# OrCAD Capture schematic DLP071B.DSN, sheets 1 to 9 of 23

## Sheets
1 PAGE21 - OUTPUT FMC CONNECTOR: size C
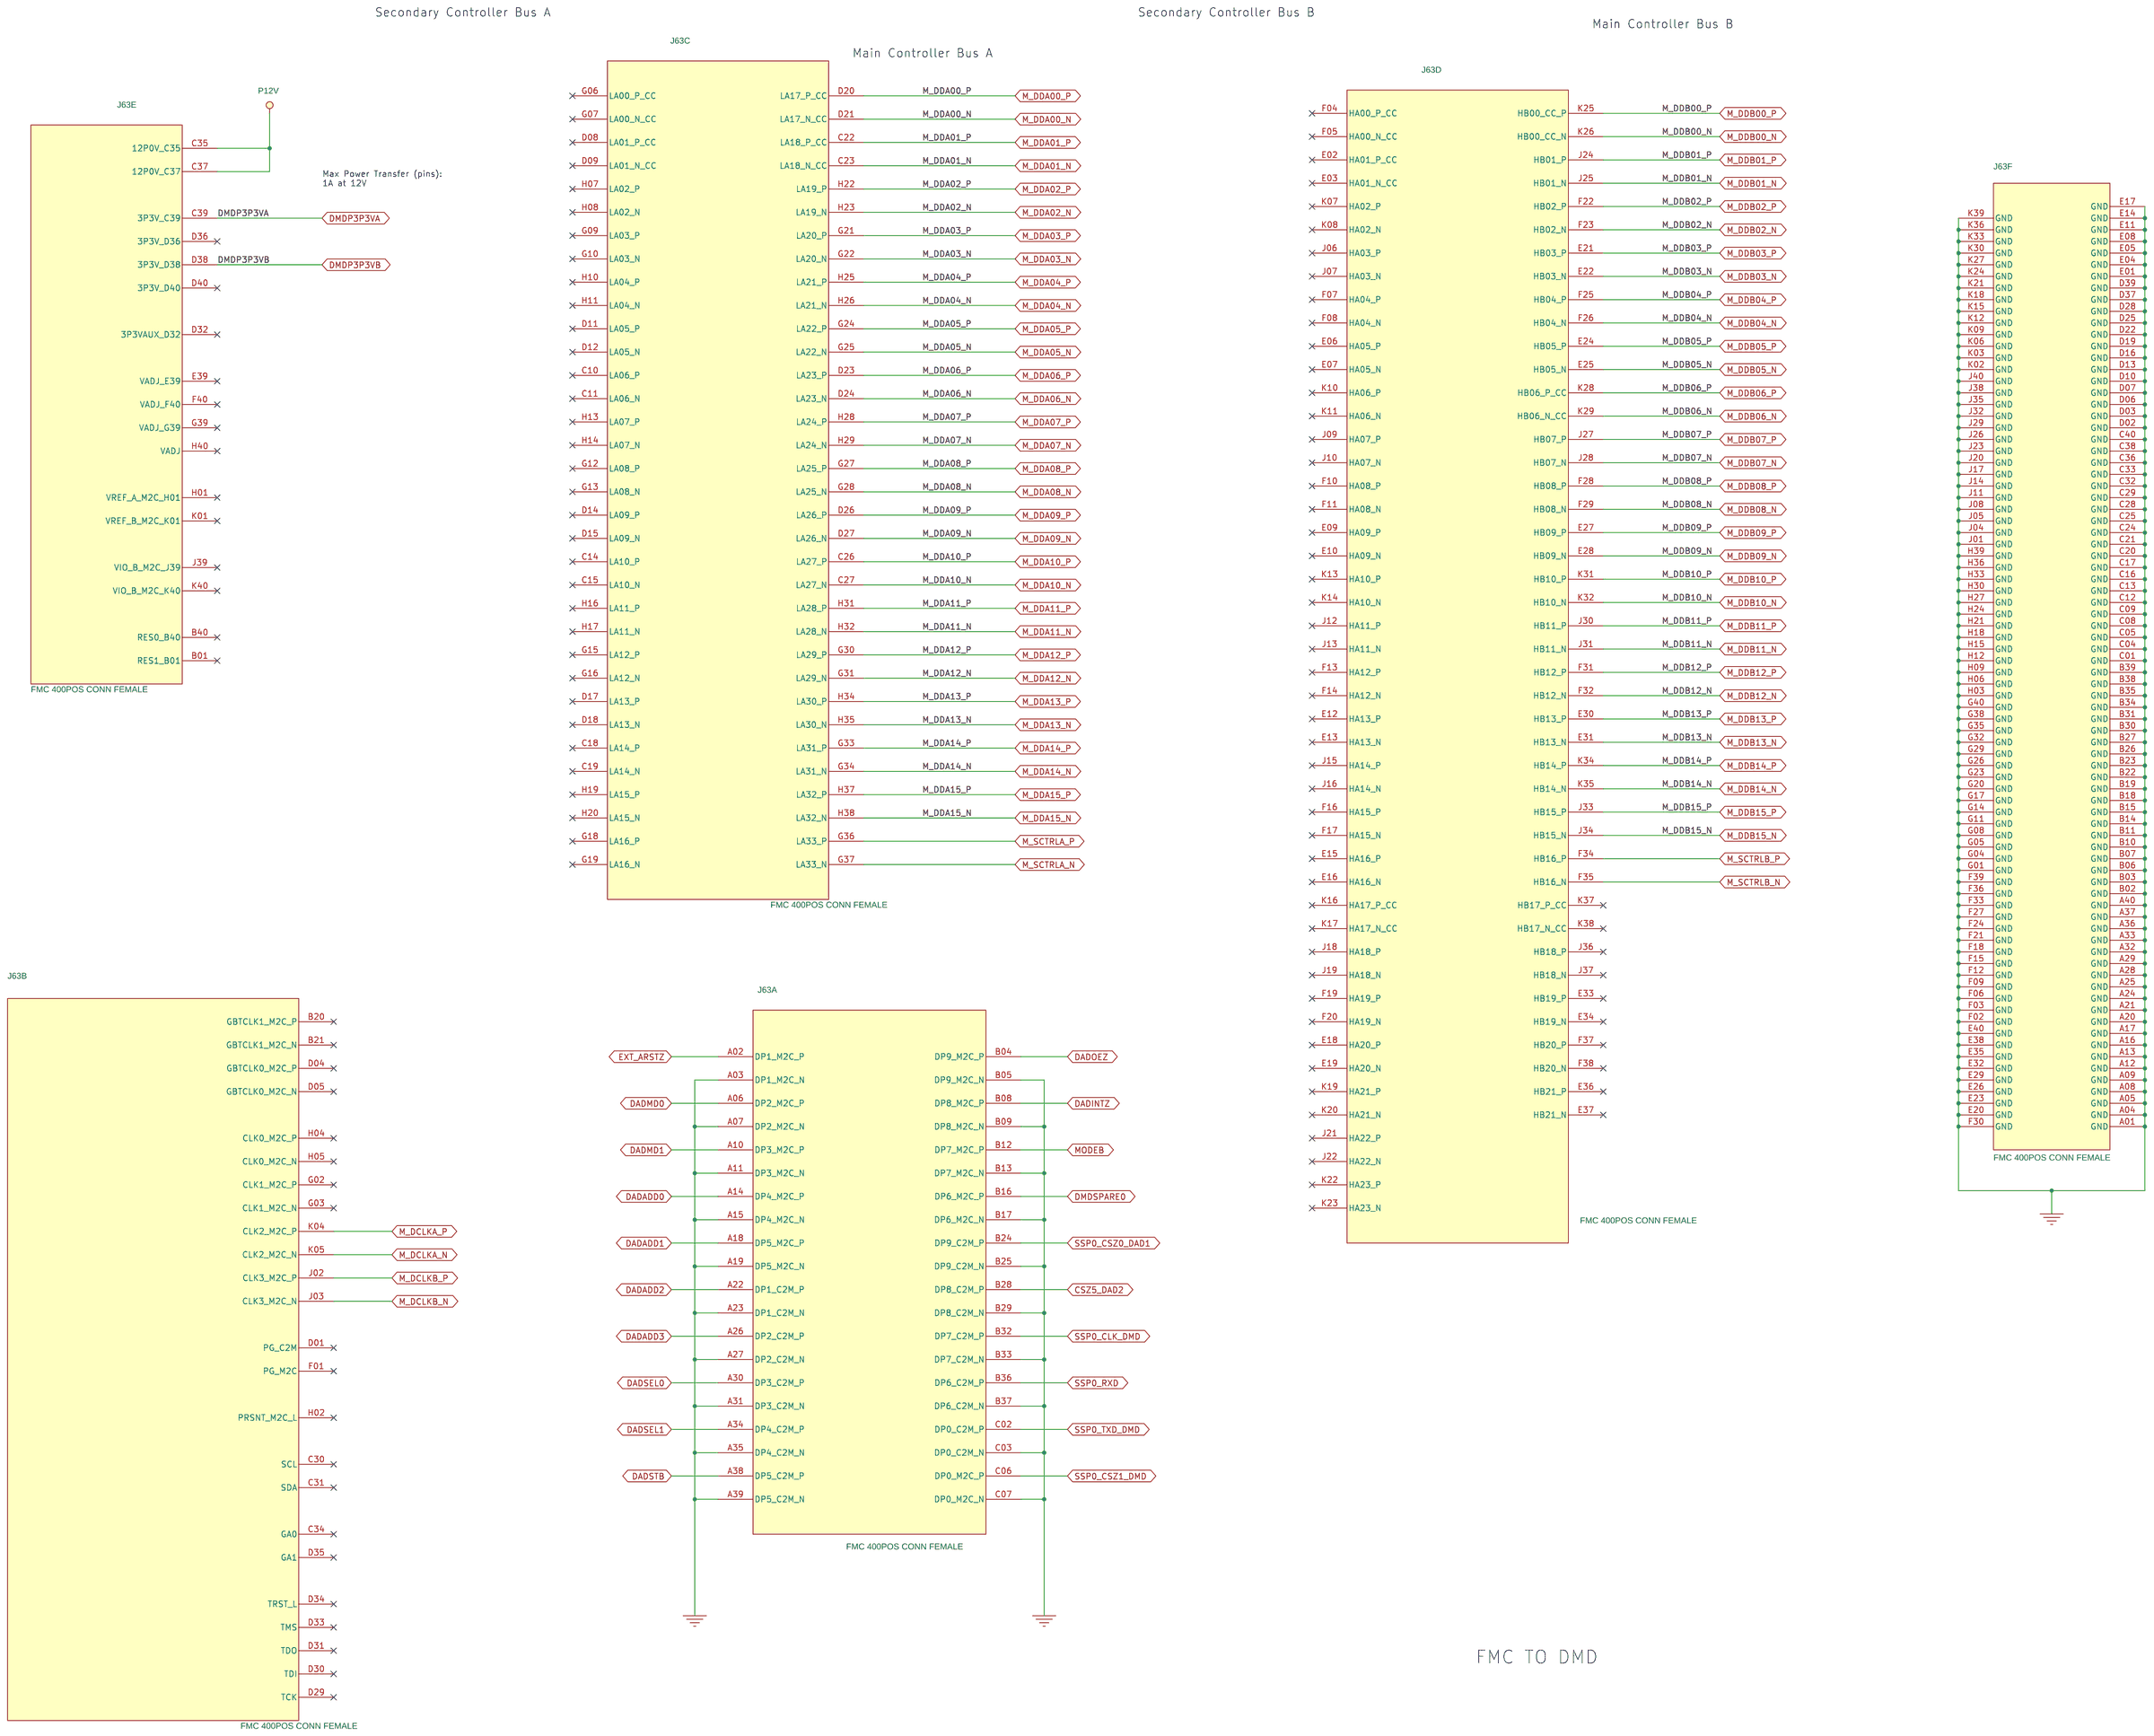
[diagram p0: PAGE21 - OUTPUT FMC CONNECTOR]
2 PAGE23 - IMPORTANT NOTICE
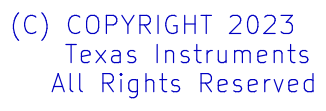
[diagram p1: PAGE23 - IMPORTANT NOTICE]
3 PAGE22 - REVISION HISTORY
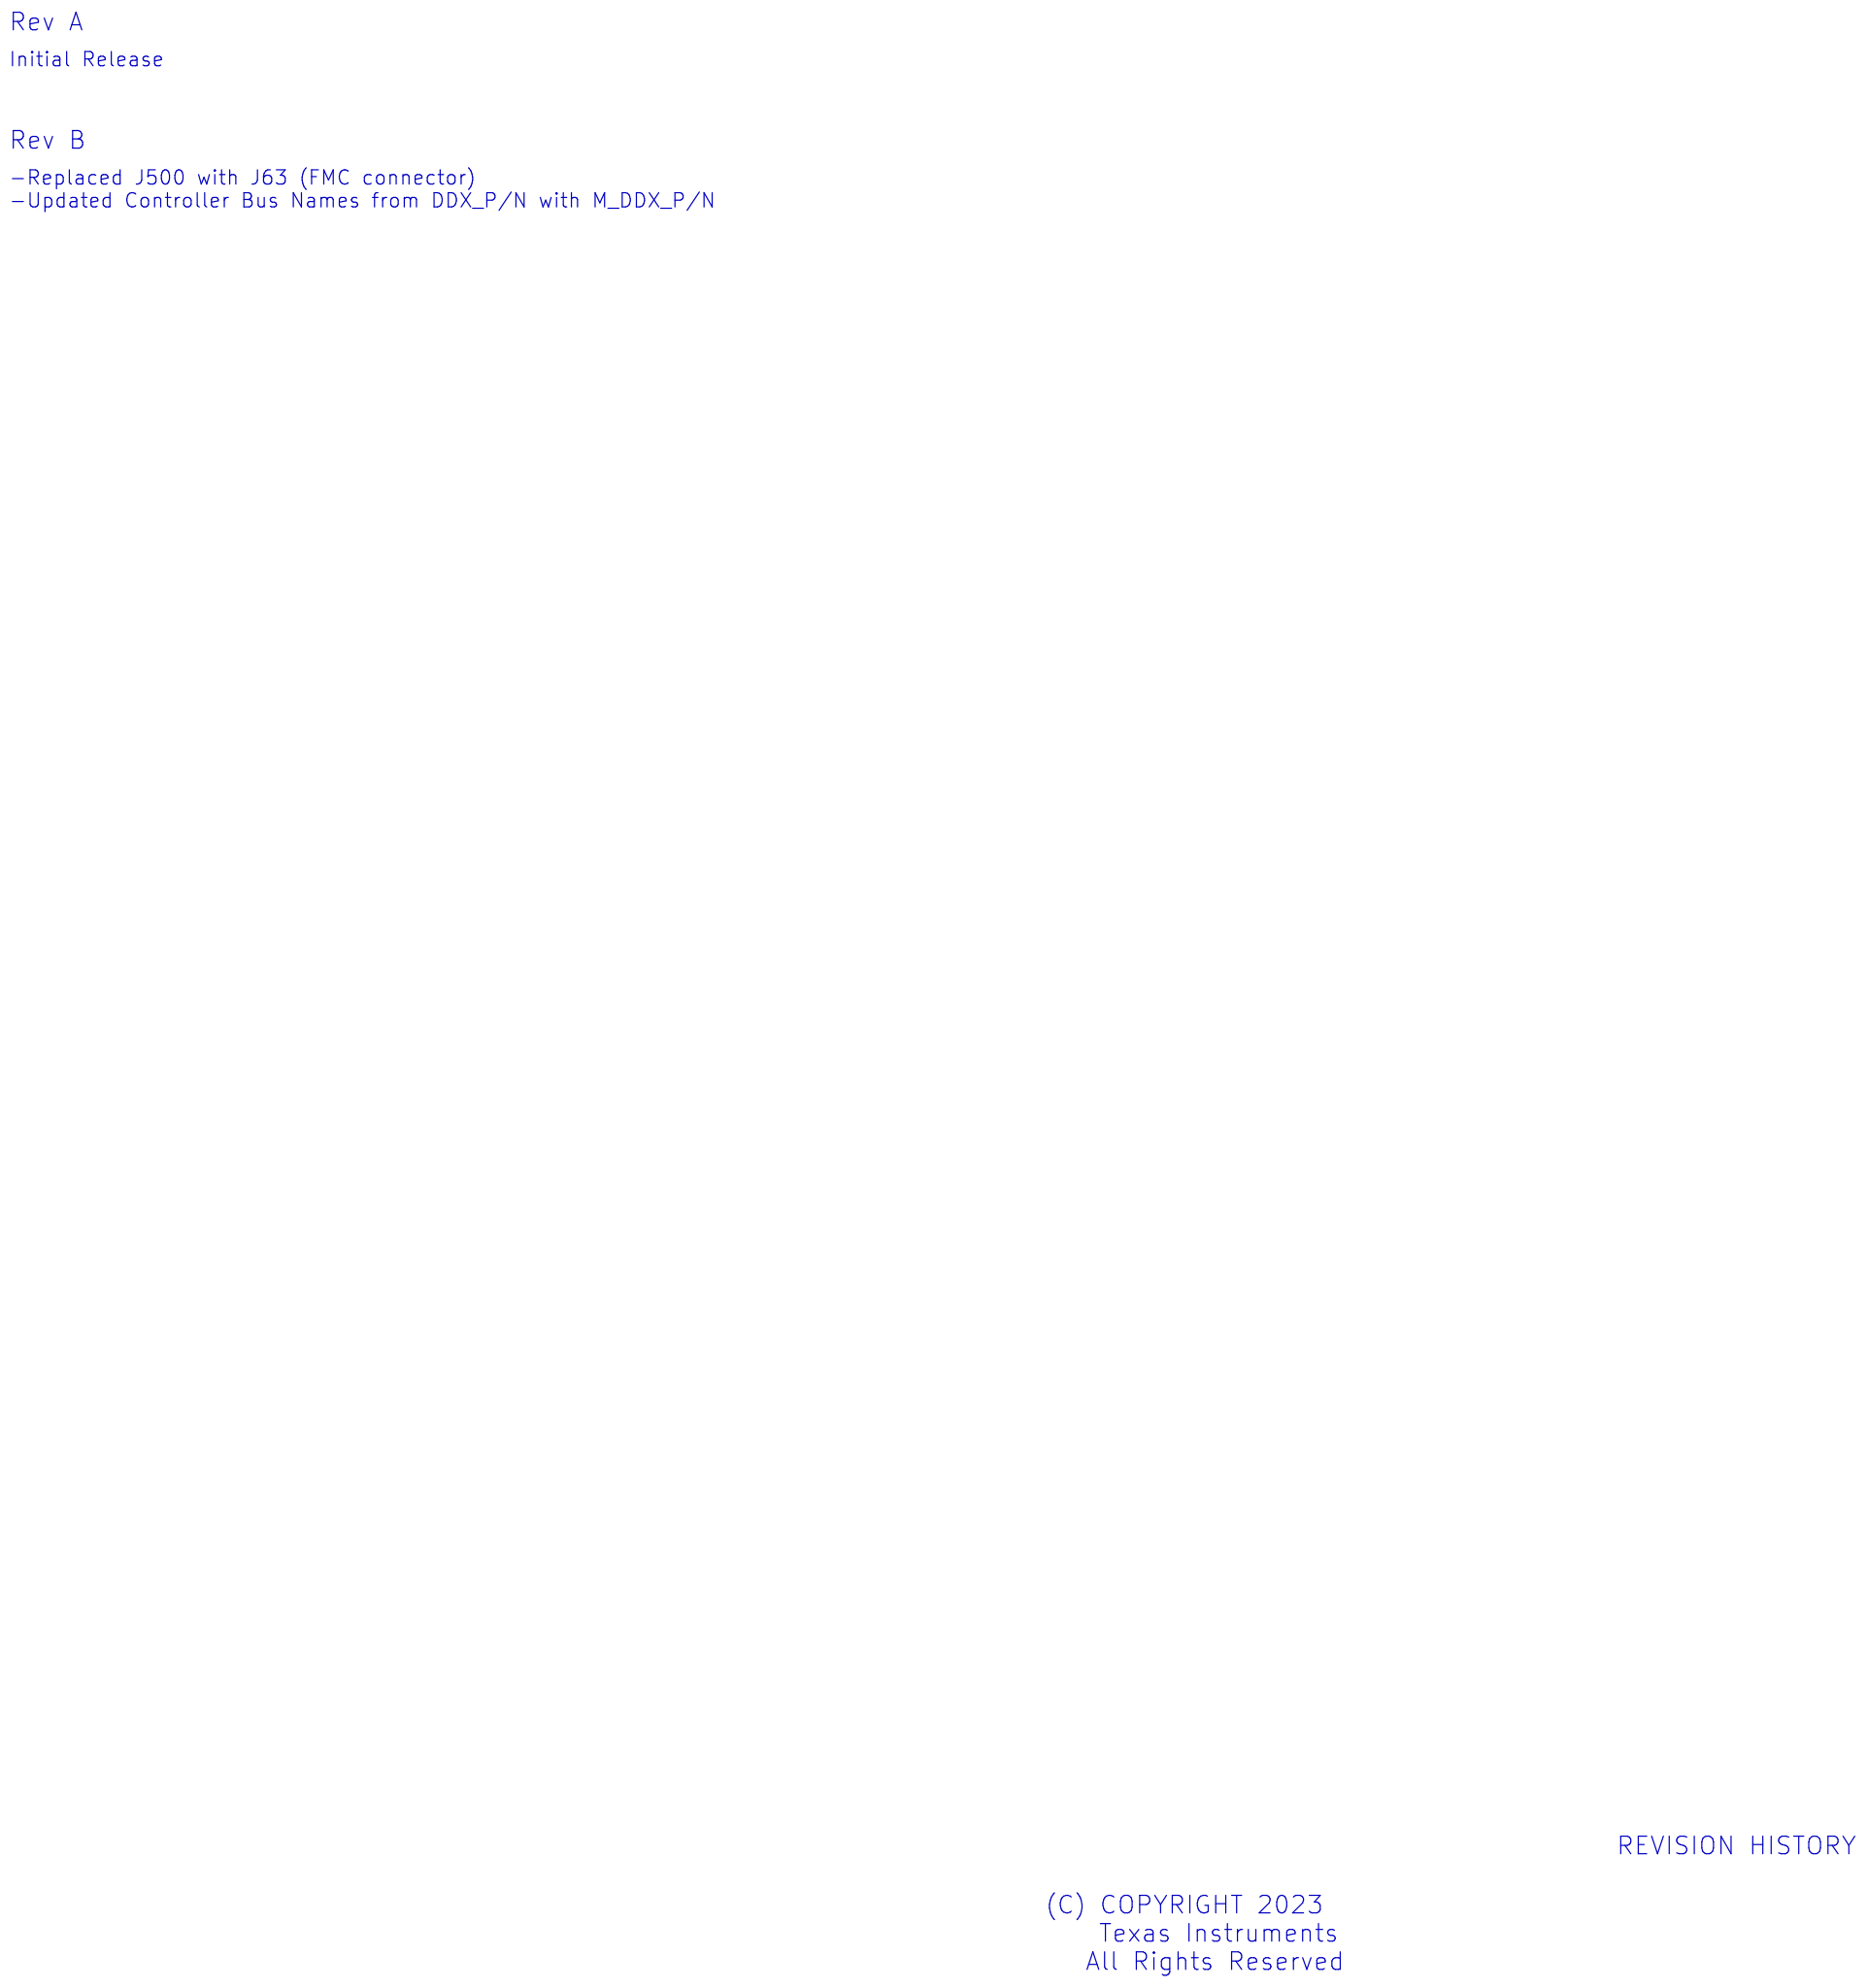
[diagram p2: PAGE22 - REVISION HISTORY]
4 PAGE20 - POWER & BYPASS CAPS: size C
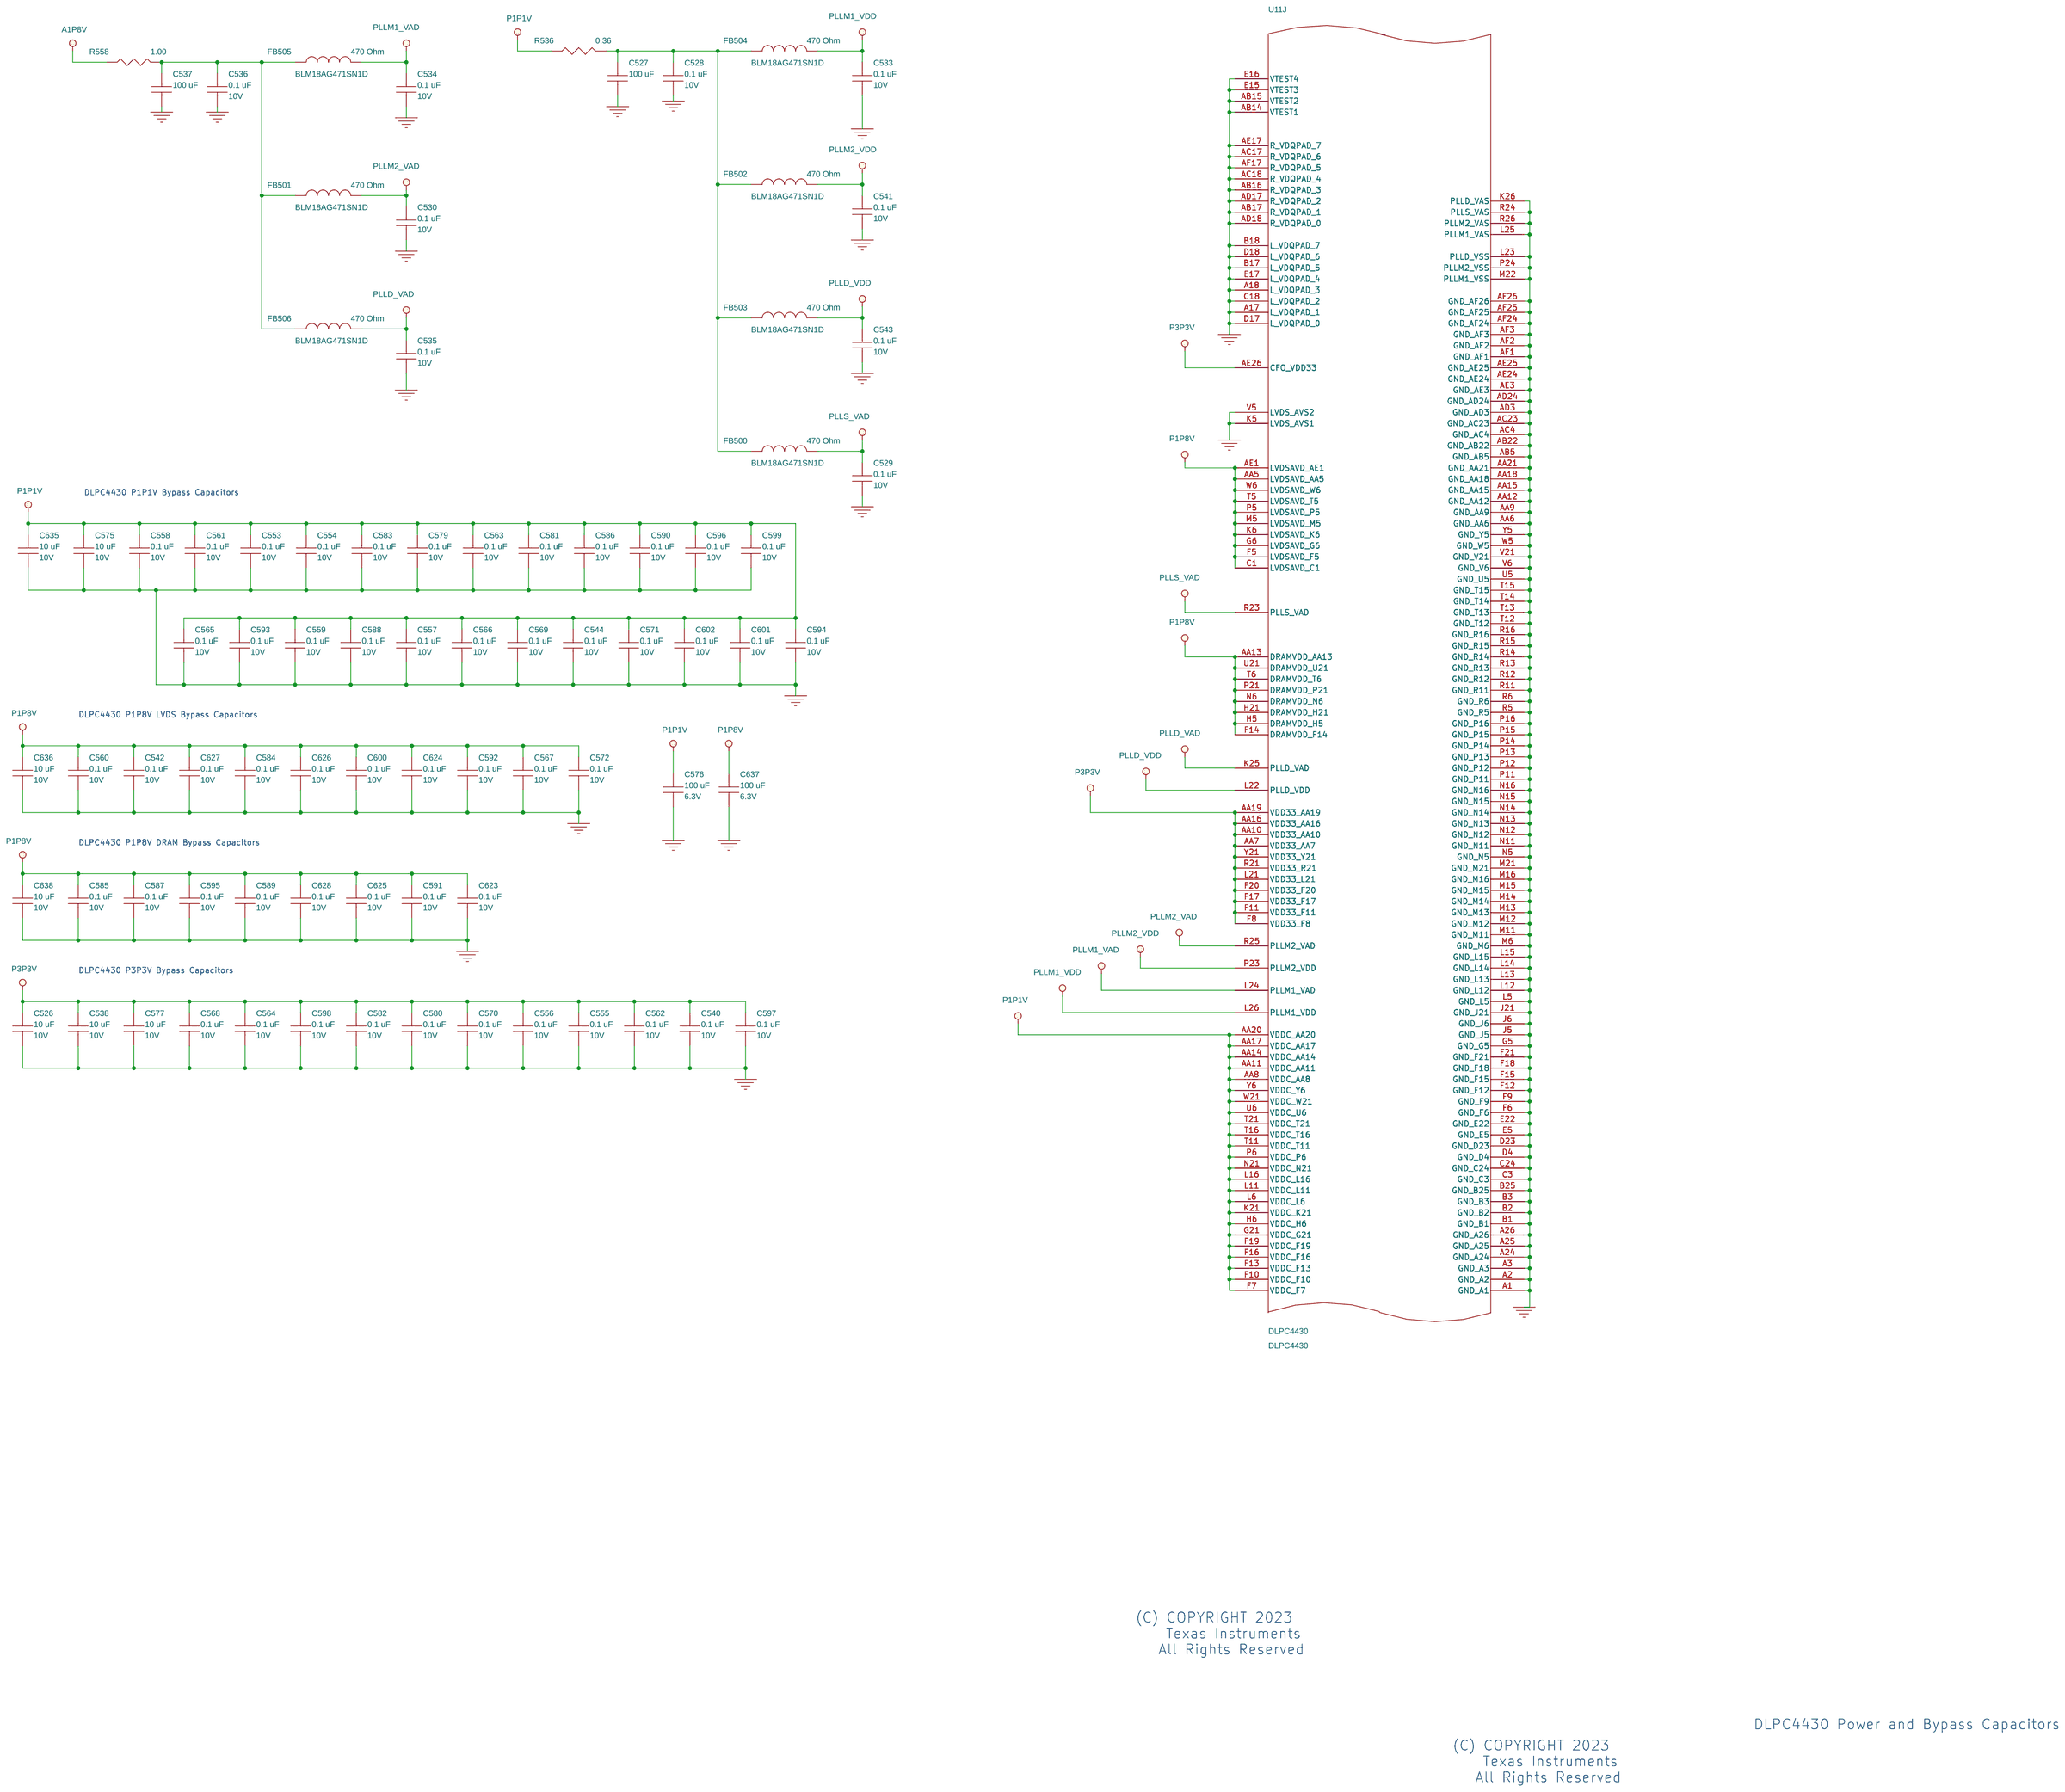
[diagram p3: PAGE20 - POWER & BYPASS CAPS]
5 PAGE19 - POINTBLANK INTERFACE: size A3
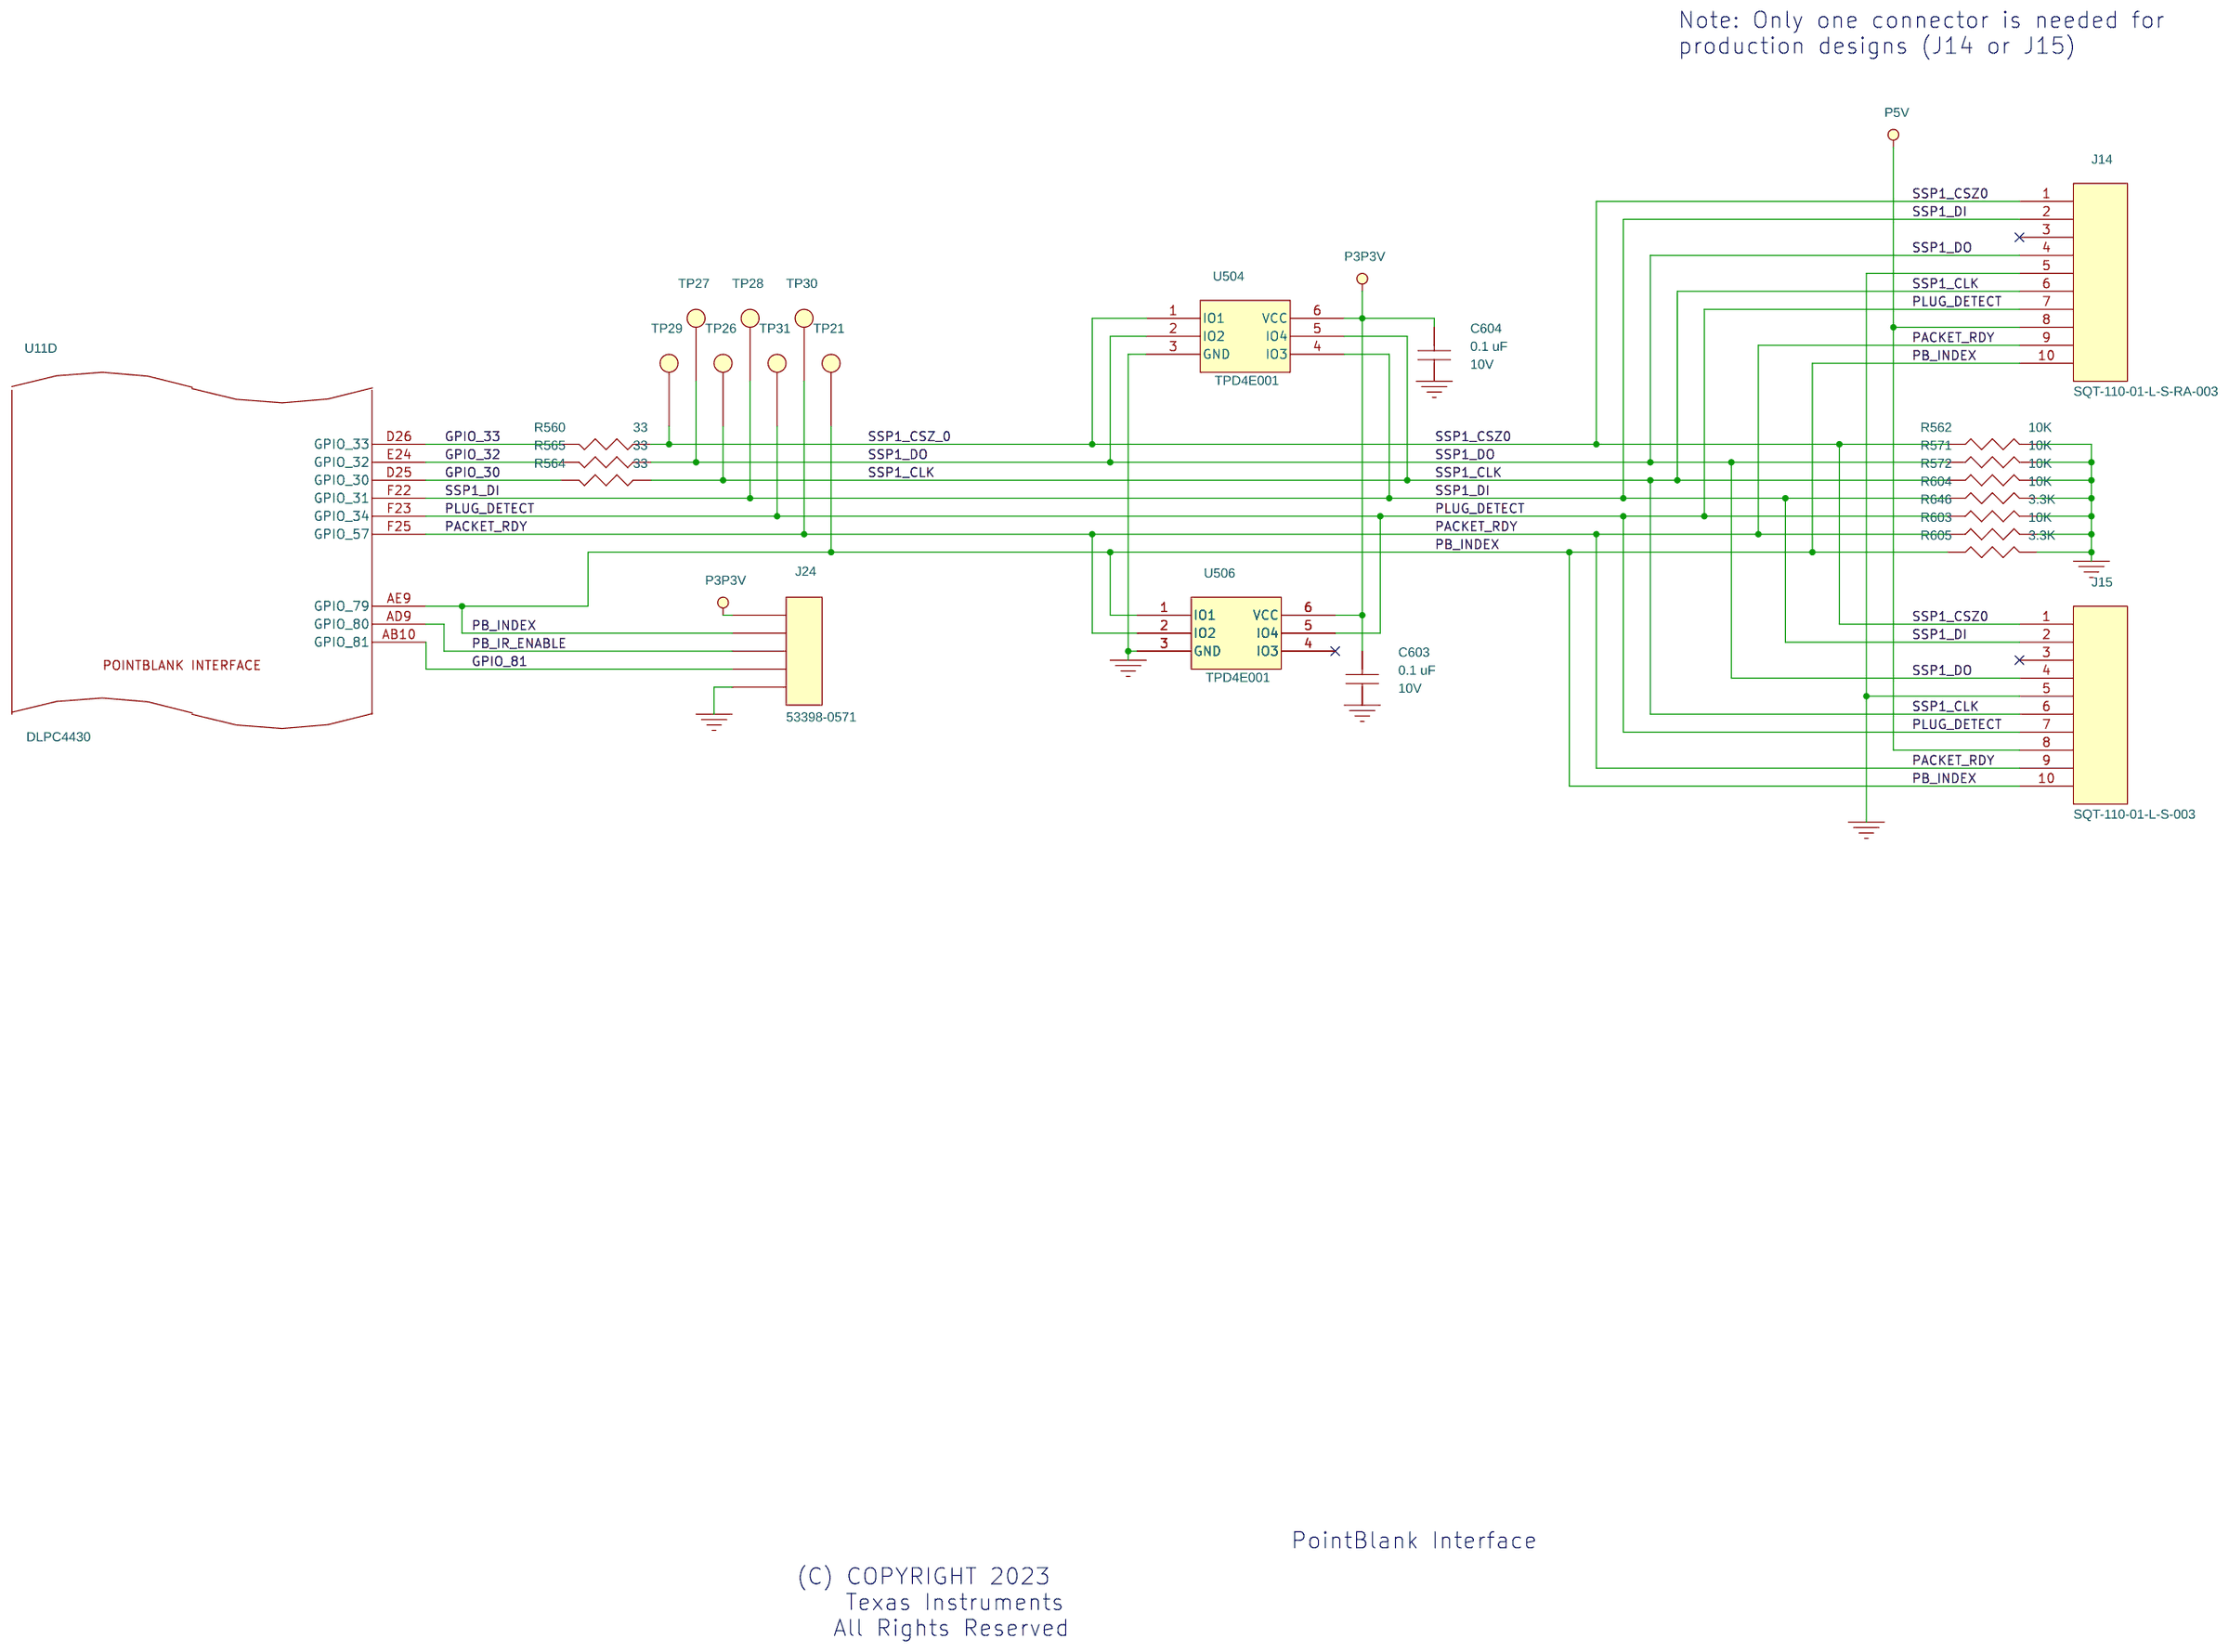
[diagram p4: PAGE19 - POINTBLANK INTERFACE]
6 PAGE18 - SSI DRIVER INTERFACES: size A3
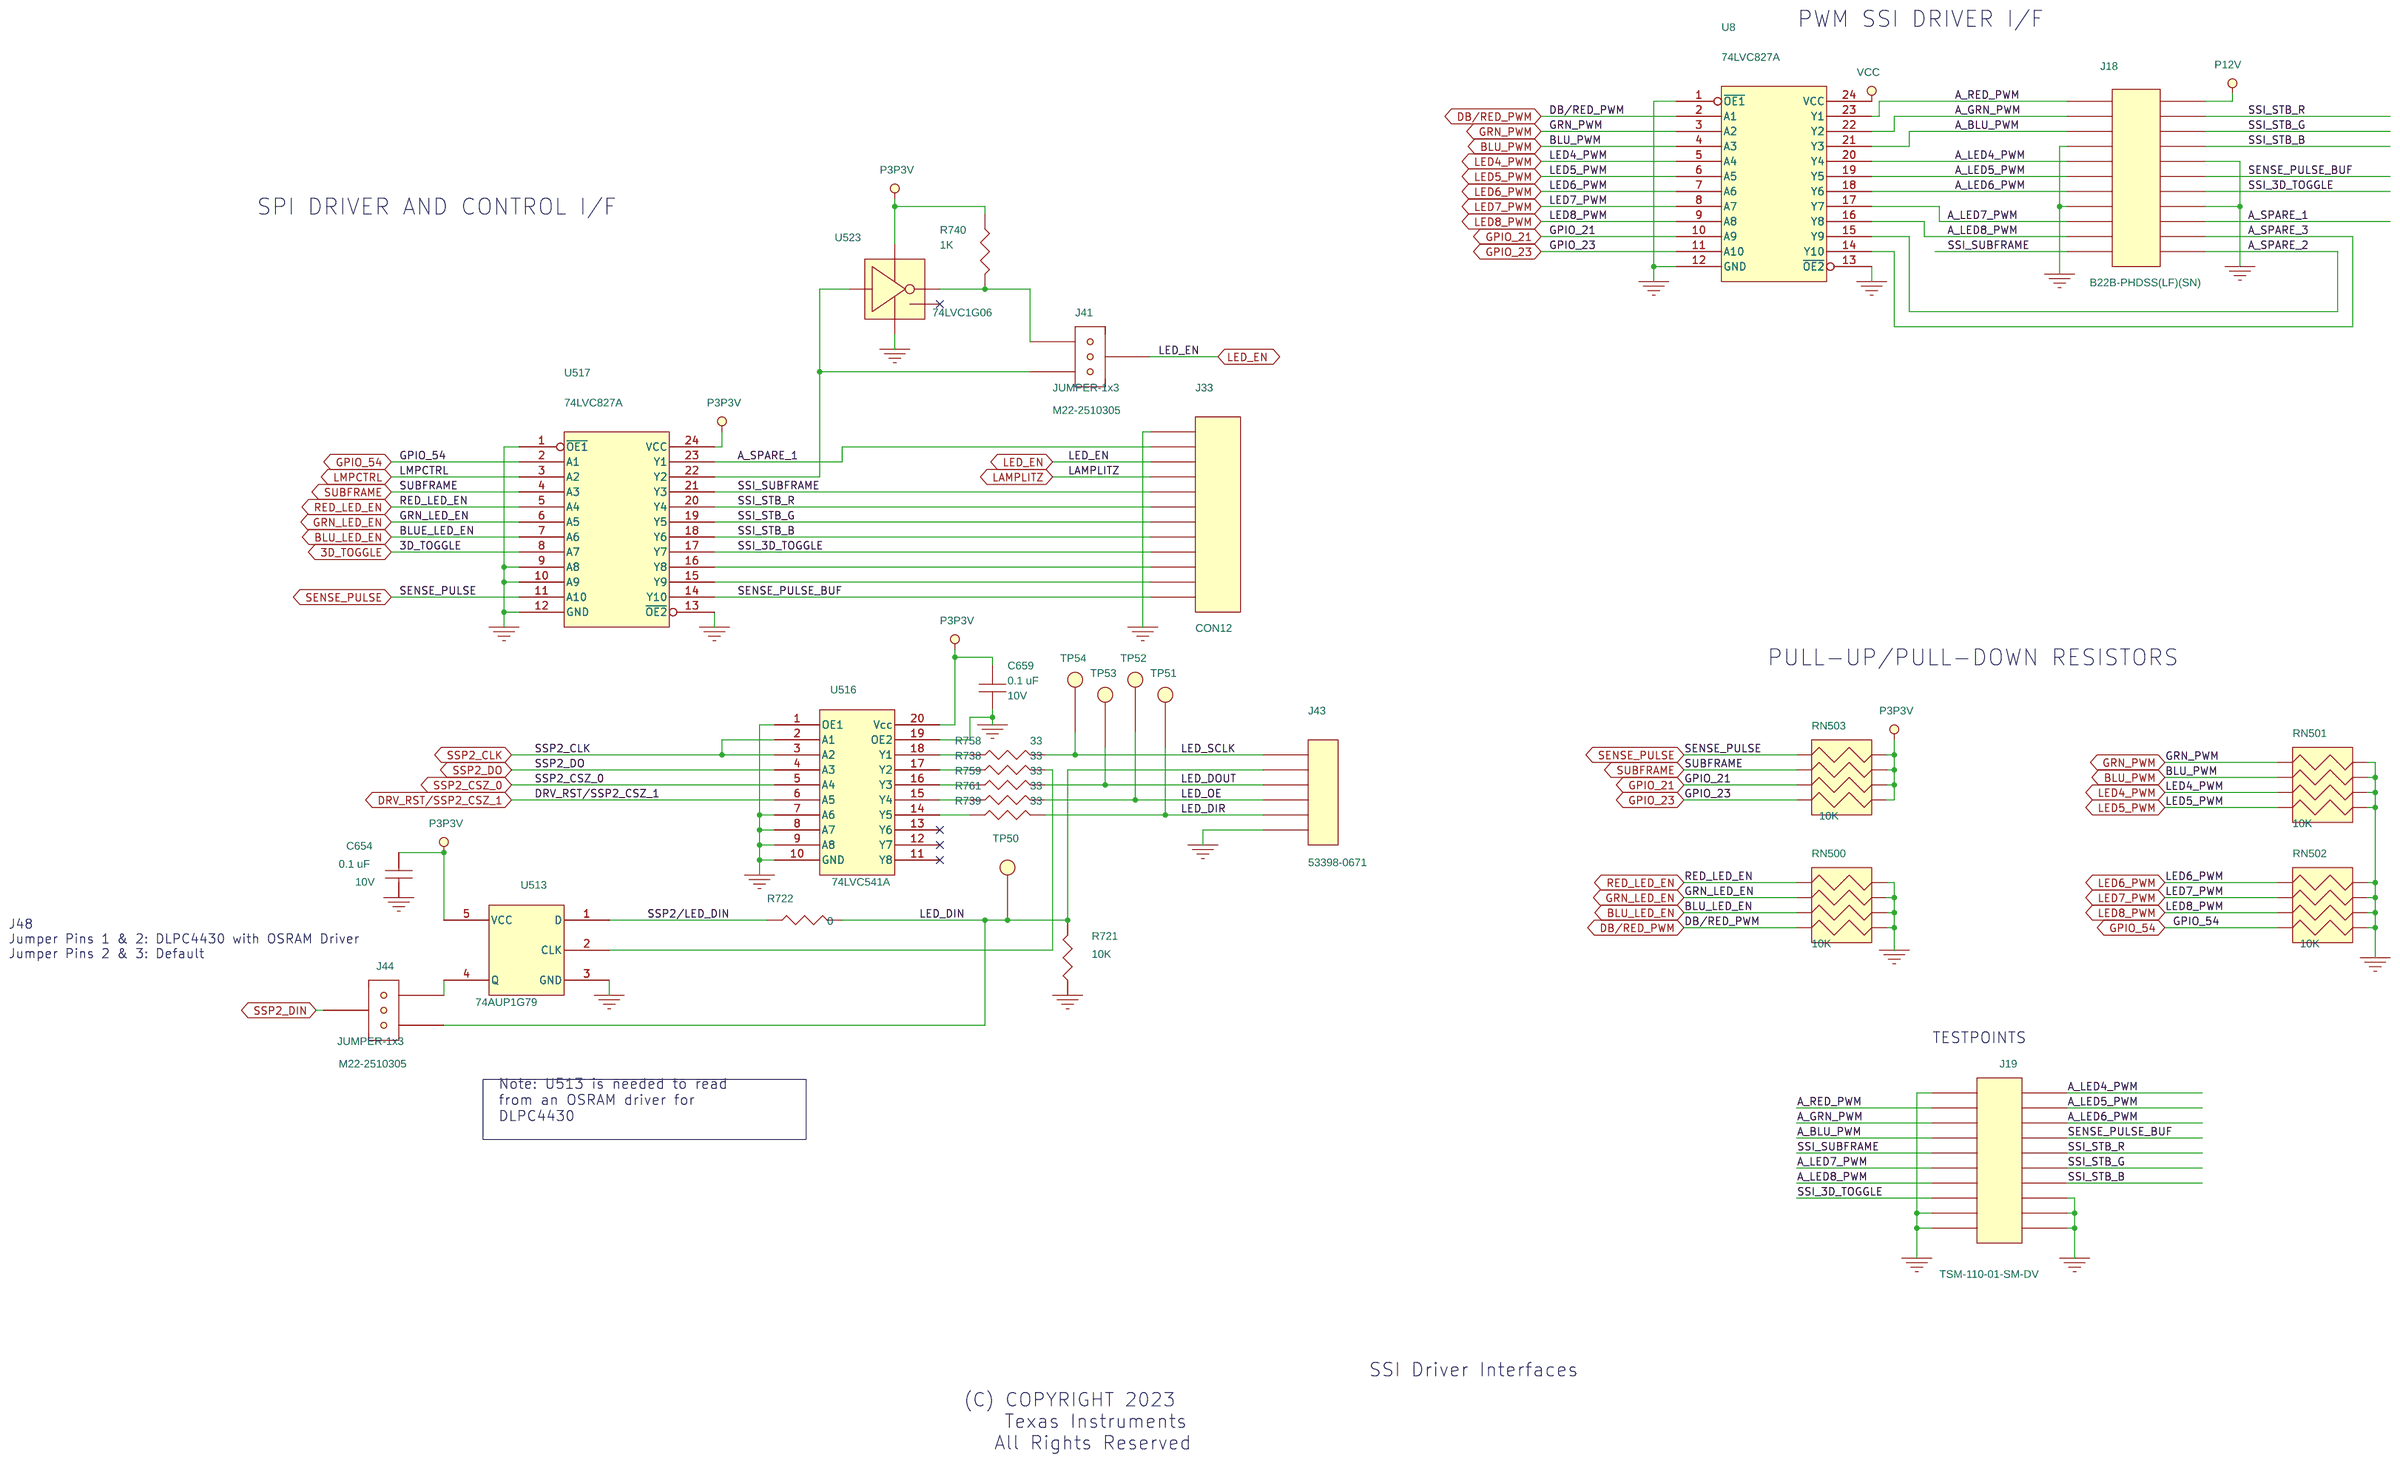
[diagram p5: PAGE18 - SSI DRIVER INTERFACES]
7 PAGE17 - LED INTERFACE: size A3
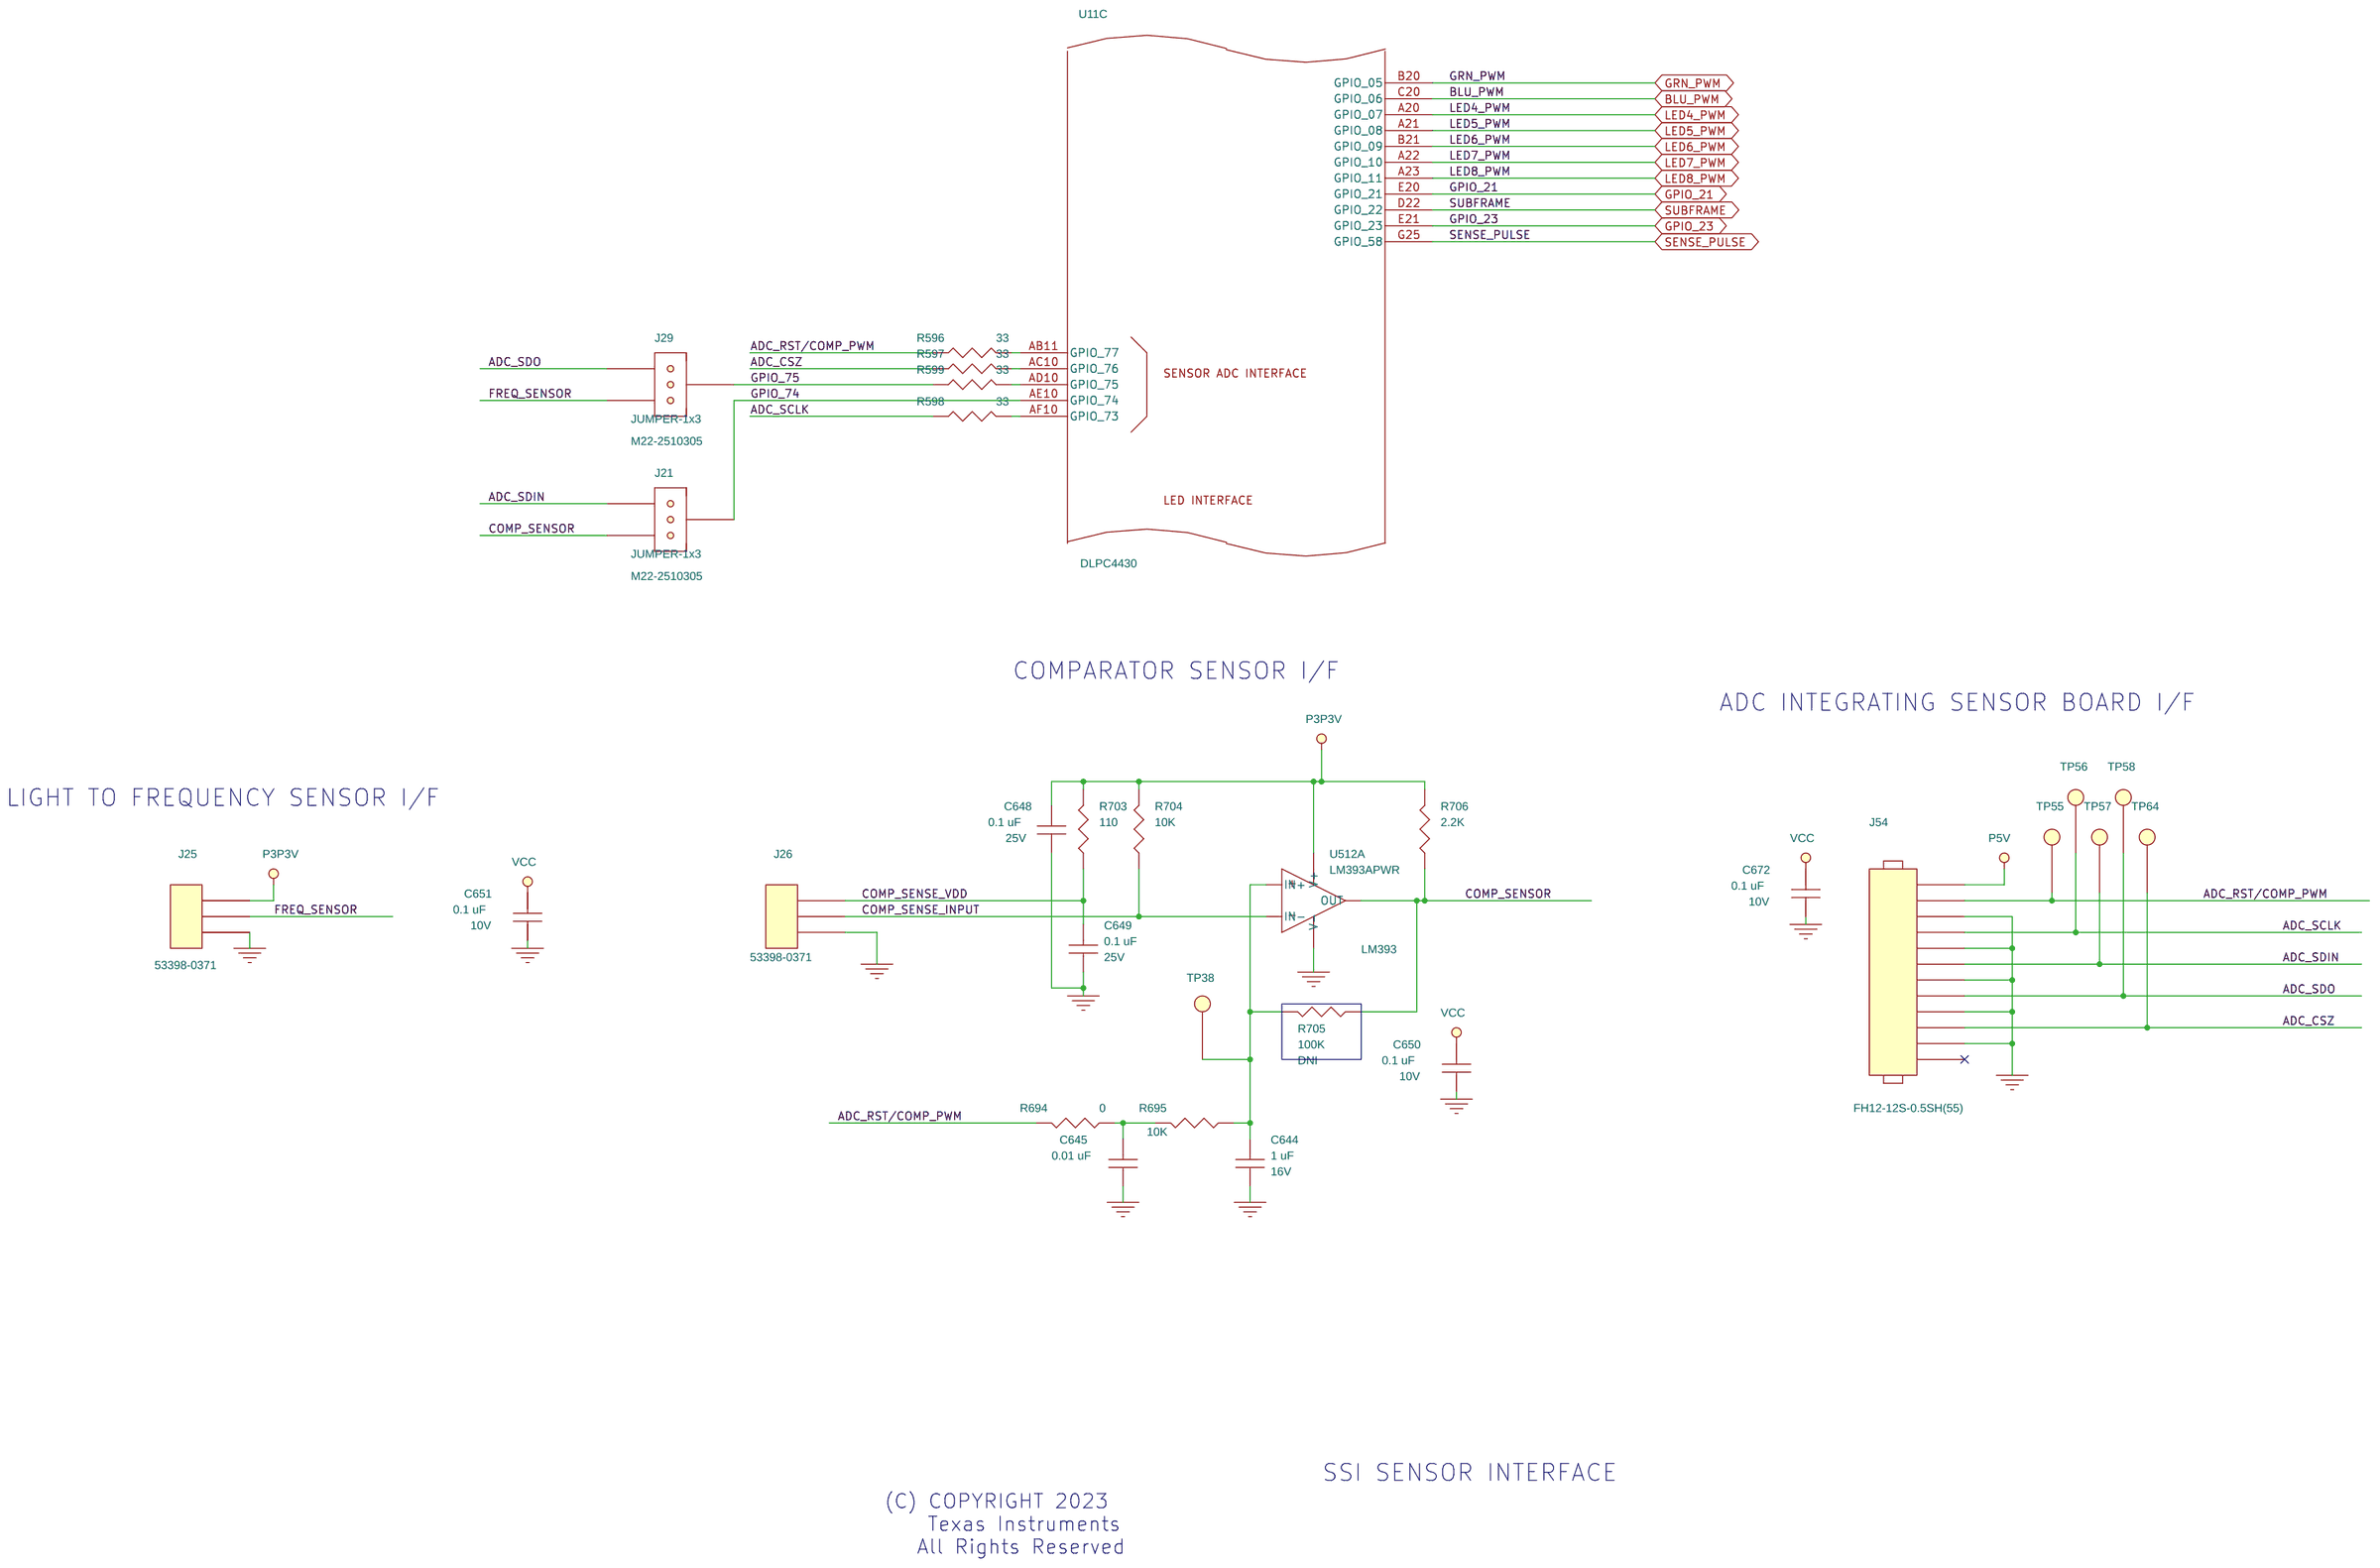
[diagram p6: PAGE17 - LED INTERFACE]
8 PAGE16 - FLASH & SRAM MEMORY: size A3
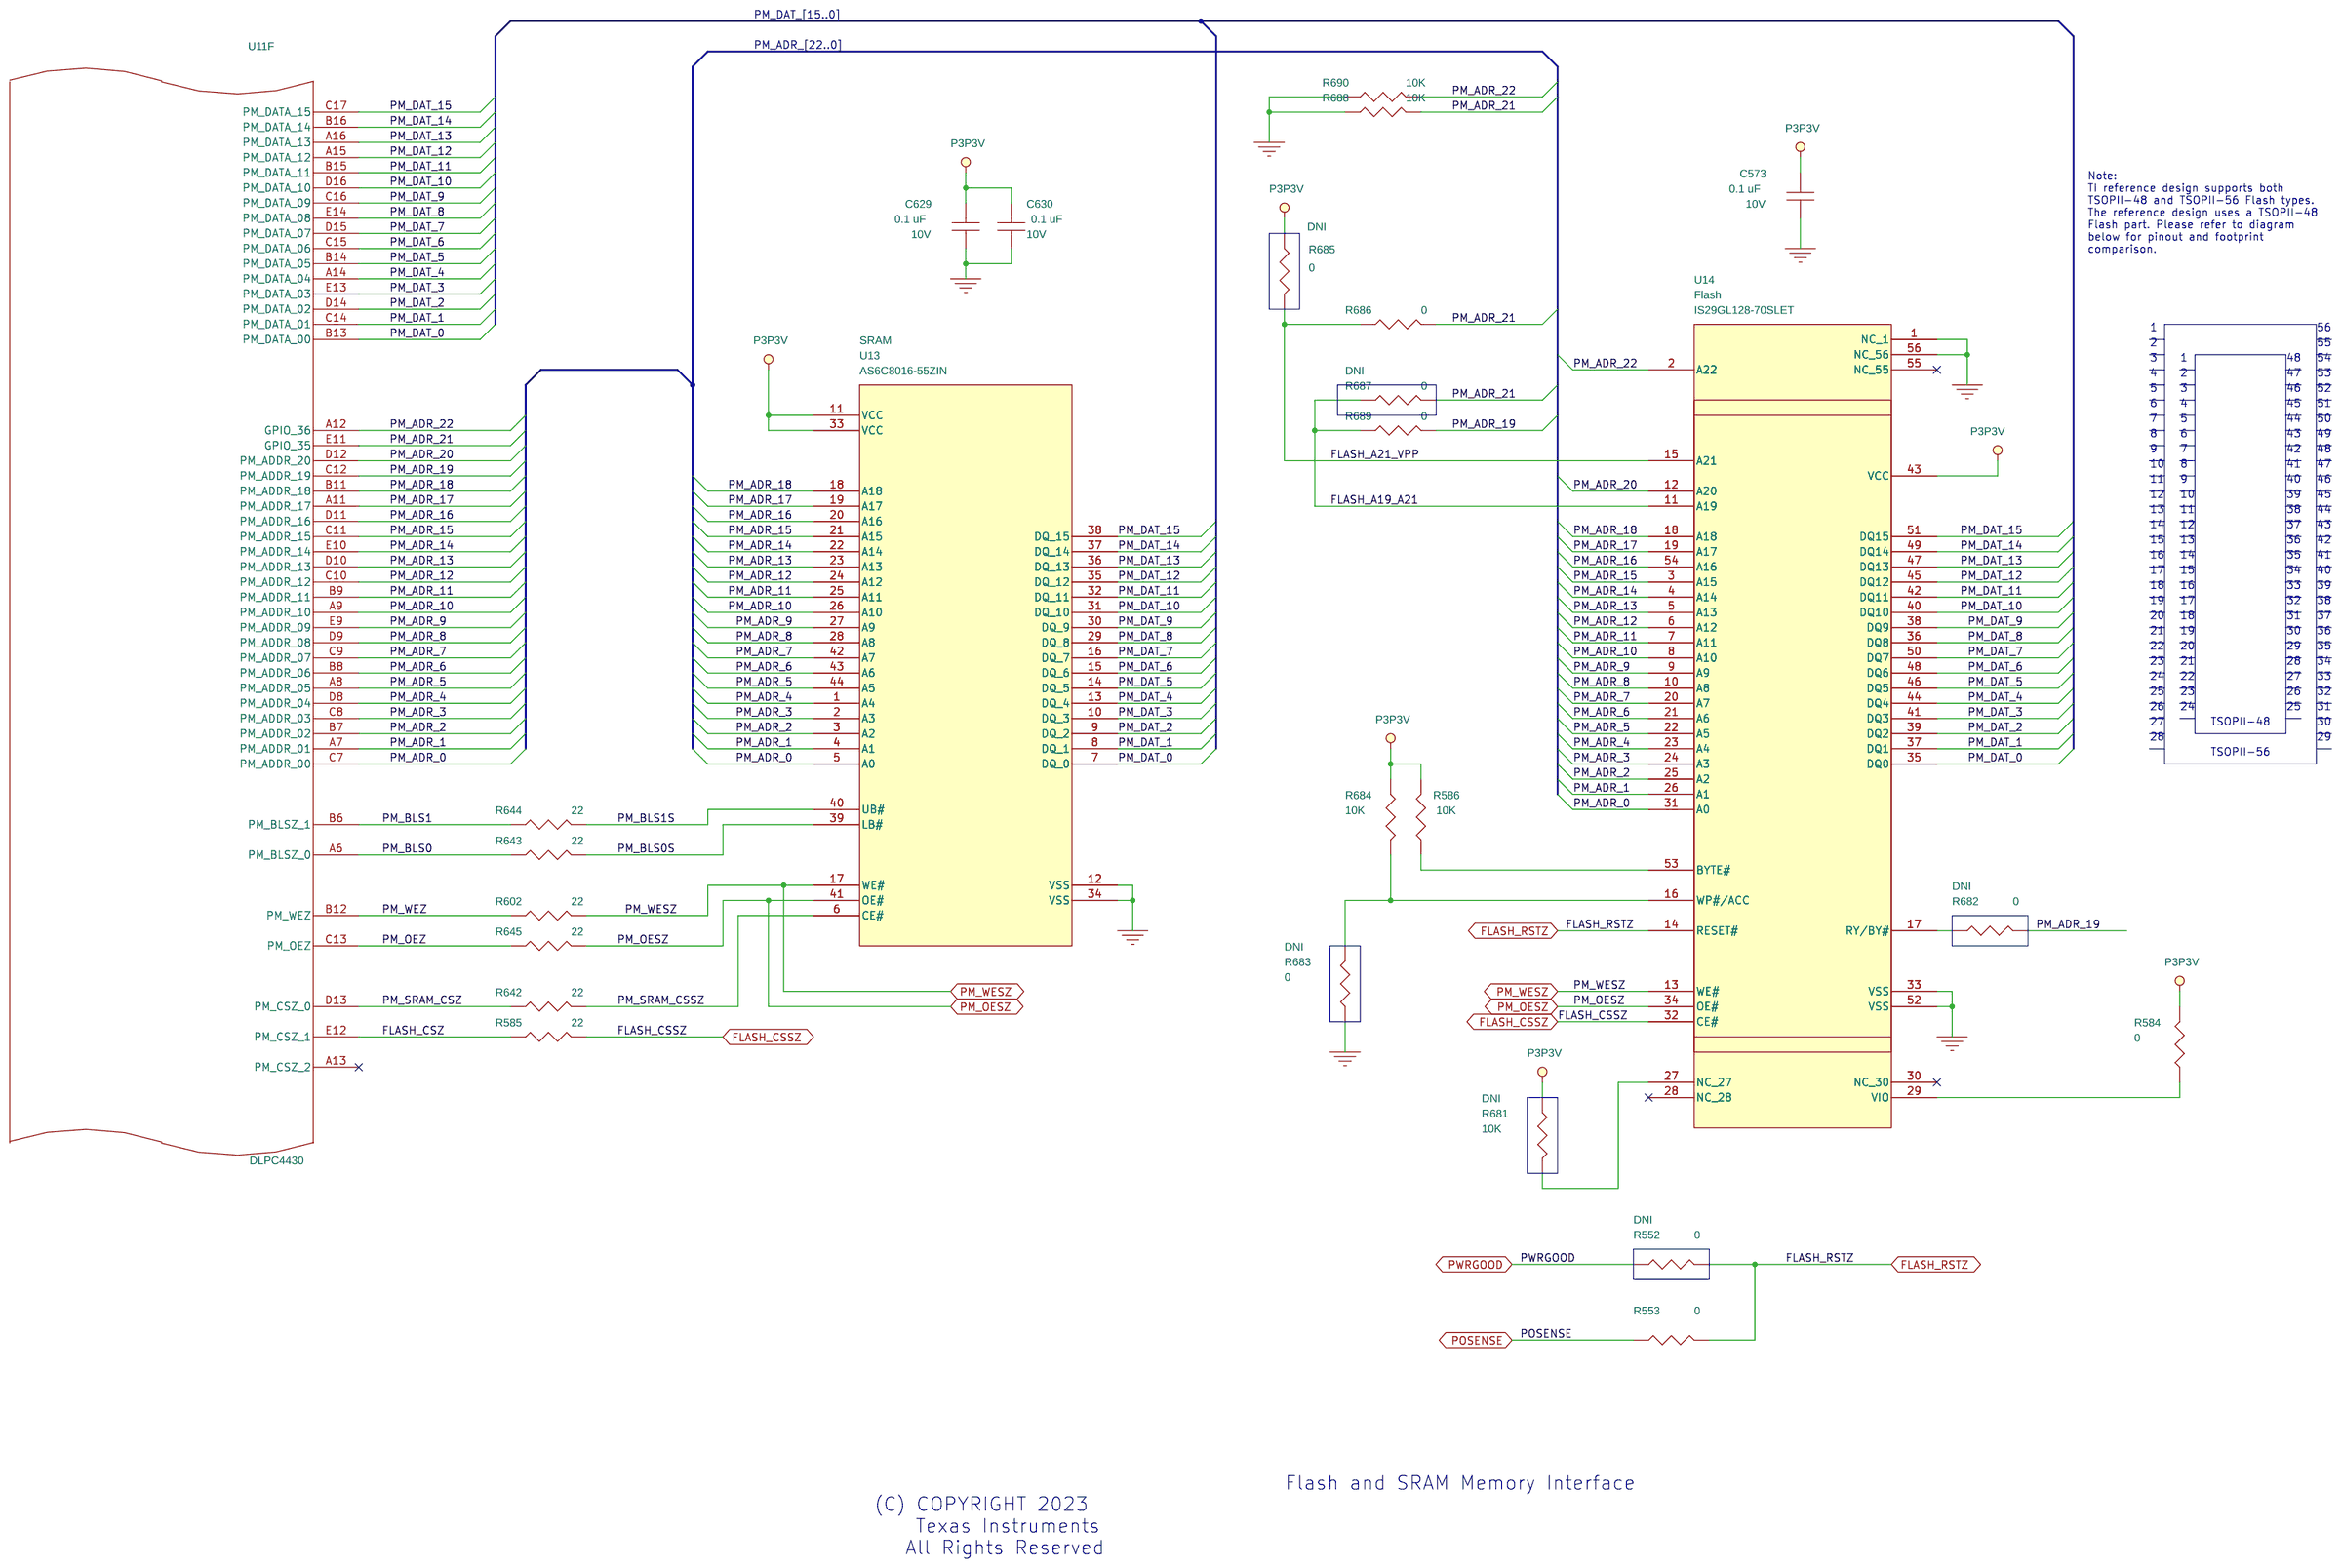
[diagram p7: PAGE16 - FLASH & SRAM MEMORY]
9 PAGE15 - RS-232, SSP, USB: size A3
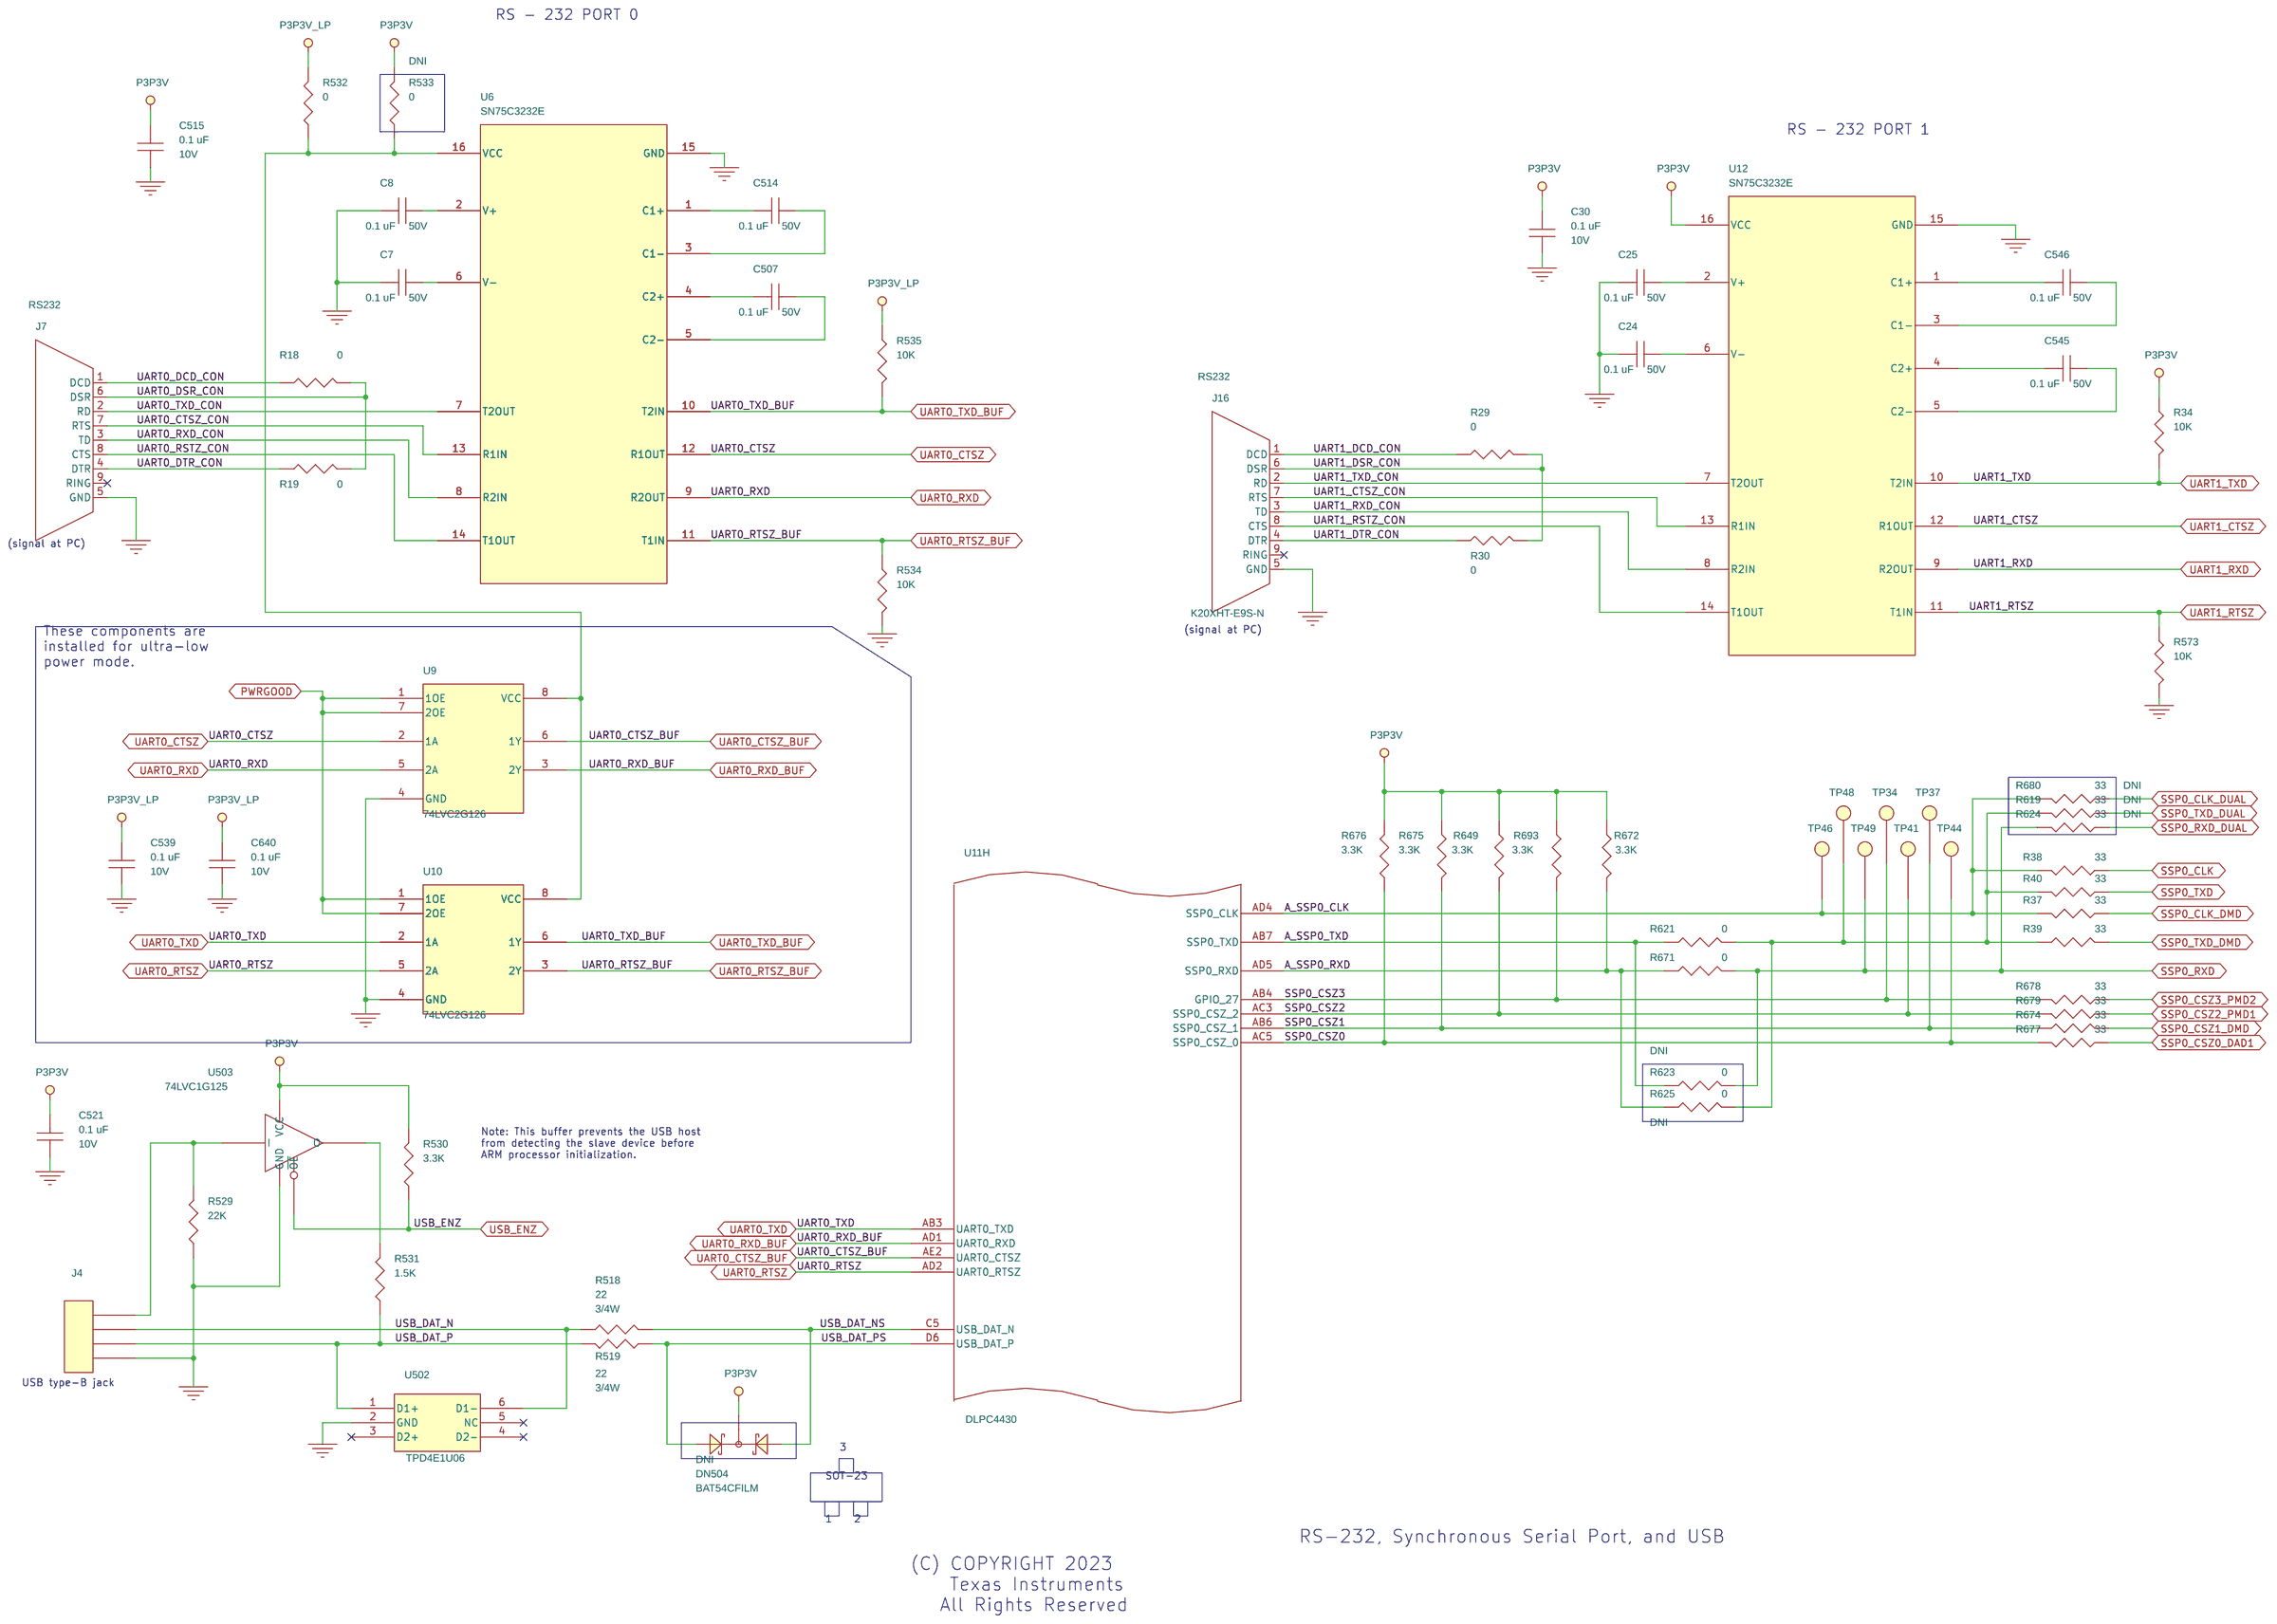
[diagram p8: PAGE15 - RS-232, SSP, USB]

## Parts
sheet PAGE15 - RS-232, SSP, USB
C7  0.1 uF  [CAP_0805]
C8  0.1 uF  [CAP_0805]
C24  0.1 uF  [CAP_0805]
C25  0.1 uF  [CAP_0805]
C30  0.1 uF  [CAP_0402]
C507  0.1 uF  [CAP_0805]
C514  0.1 uF  [CAP_0805]
C515  0.1 uF  [CAP_0402]
C521  0.1 uF  [CAP_0402]
C539  0.1 uF  [CAP_0402]
C545  0.1 uF  [CAP_0805]
C546  0.1 uF  [CAP_0805]
C640  0.1 uF  [CAP_0402]
DN504  BAT54C  [SOT23AVXC]
J4  CON4  [CONN4-67068-1000-a_MOLEX]
J7  RS232  [KYCON-CN9SMTA]
J16  RS232  [KYCON-CN9SMTA]
R18  0  [RES_0402]
R19  0  [RES_0402]
R29  0  [RES_0402]
R30  0  [RES_0402]
R34  10K  [RES_0402]
R37  33  [RES_0402]
R38  33  [RES_0402]
R39  33  [RES_0402]
R40  33  [RES_0402]
R518  22  [RES_2010]
R519  22  [RES_2010]
R529  22K  [RES_0603]
R530  3.3K  [RES_0402]
R531  1.5K  [RES_0603]
R532  0  [RES_0402]
R533  0  [RES_0402]
R534  10K  [RES_0402]
R535  10K  [RES_0402]
R573  10K  [RES_0402]
R619  33  [RES_0402]
R621  0  [RES_0402]
R623  0  [RES_0402]
R624  33  [RES_0402]
R625  0  [RES_0402]
R649  3.3K  [RES_0402]
R671  0  [RES_0402]
R672  3.3K  [RES_0402]
R674  33  [RES_0402]
R675  3.3K  [RES_0402]
R676  3.3K  [RES_0402]
R677  33  [RES_0402]
R678  33  [RES_0402]
R679  33  [RES_0402]
R680  33  [RES_0402]
R693  3.3K  [RES_0402]
TP34  Testpoint  [TP]
TP37  Testpoint  [TP]
TP41  Testpoint  [TP]
TP44  Testpoint  [TP]
TP46  Testpoint  [TP]
TP48  Testpoint  [TP]
TP49  Testpoint  [TP]
U6  SN75C3232E  [SOIC16-PW_TI]
U9  74LVC2G126  [SSOP_8]
U10  74LVC2G126  [SSOP_8]
U11  DLPC4430  [BGA552-DDP4422_TI_MOD]  (sections A,B,C,D,E,F,G,H,I,J)
U12  SN75C3232E  [SOIC16-PW_TI]
U502  TPD4E1U06  [SOIC6-DBV_TI]
U503  74LVC1G125  [SOT23-DBV_TI]
sheet PAGE16 - FLASH & SRAM MEMORY
C573  0.1 uF  [CAP_0402]
C629  0.1 uF  [CAP_0402]
C630  0.1 uF  [CAP_0402]
R552  0  [RES_0402]
R553  0  [RES_0402]
R584  0  [RES_0402]
R585  22  [RES_0402]
R586  10K  [RES_0402]
R602  22  [RES_0402]
R642  22  [RES_0402]
R643  22  [RES_0402]
R644  22  [RES_0402]
R645  22  [RES_0402]
R681  10K  [RES_0402]
R682  0  [RES_0402]
R683  0  [RES_0402]
R684  10K  [RES_0402]
R685  0  [RES_0402]
R686  0  [RES_0402]
R687  0  [RES_0402]
R688  10K  [RES_0402]
R689  0  [RES_0402]
R690  10K  [RES_0402]
U13  SRAM  [TSOPII_44]
U14  Flash  [TSOP_56_48_DUAL_SKT]
sheet PAGE17 - LED INTERFACE
C644  1 uF  [CAP_0805]
C645  0.01 uF  [CAP_0603]
C648  0.1 uF  [CAP_0603]
C649  0.1 uF  [CAP_0603]
C650  0.1 uF  [CAP_0402]
C651  0.1 uF  [CAP_0402]
C672  0.1 uF  [CAP_0402]
J21  JUMPER-1x3  [HDR1X3-TMM1030X-X-S_SAM]
J25  CON3  [CN3_53398_MOLEX]
J26  CON3  [CN3_53398_MOLEX]
J29  JUMPER-1x3  [HDR1X3-TMM1030X-X-S_SAM]
J54  12 HEADER  [CONN12-FH12_HRS]
R596  33  [RES_0402]
R597  33  [RES_0402]
R598  33  [RES_0402]
R599  33  [RES_0402]
R694  0  [RES_0402]
R695  10K  [RES_0402]
R703  110  [RES_0805]
R704  10K  [RES_0402]
R705  100K  [RES_0402]
R706  2.2K  [RES_0603]
TP38  Testpoint  [TP]
TP55  Testpoint  [TP]
TP56  Testpoint  [TP]
TP57  Testpoint  [TP]
TP58  Testpoint  [TP]
TP64  Testpoint  [TP]
U512  LM393  [SOIC8-PW_TI]  (section A)
sheet PAGE18 - SSI DRIVER INTERFACES
C654  0.1 uF  [CAP_0402]
C659  0.1 uF  [CAP_0402]
J18  CON22  [CONN22-B22B-PHD_JST]
J19  CON20A  [CONN20-TSM-110-0X-X-DV-A_SAMTEC]
J33  CON12  [CONN12-53398_MOLEX]
J41  JUMPER-1x3  [HDR1X3-TMM1030X-X-S_SAM]
J43  CON6  [CONN6-53398-0690-a_MOLEX]
J44  JUMPER-1x3  [HDR1X3-TMM1030X-X-S_SAM]
R721  10K  [RES_0402]
R722  0  [RES_0402]
R738  33  [RES_0402]
R739  33  [RES_0402]
R740  1K  [RES_0402]
R758  33  [RES_0402]
R759  33  [RES_0402]
R761  33  [RES_0402]
RN500  10K  [RNET8-EXB38V_PAN]
RN501  10K  [RNET8-EXB38V_PAN]
RN502  10K  [RNET8-EXB38V_PAN]
RN503  10K  [RNET8-EXB38V_PAN]
TP50  Testpoint  [TP]
TP51  Testpoint  [TP]
TP52  Testpoint  [TP]
TP53  Testpoint  [TP]
TP54  Testpoint  [TP]
U8  74LVC827A  [SOIC24-PW_TI]
U513  74AUP1G79  [SOIC5-DBV_TI]
U516  74LVC541A  [SOIC20-DGV_TI]
U517  74LVC827A  [SOIC24-PW_TI]
U523  74LVC1G06  [SOIC5-DBV_TI]
sheet PAGE19 - POINTBLANK INTERFACE
C603  0.1 uF  [CAP_0402]
C604  0.1 uF  [CAP_0402]
J14  CONN10RA  [CONN10-SQT-RA-REV_SAM]
J15  CONN10  [CONN10-SQT_SAM]
J24  CON5  [CONN5-53398-0590-a_MOLEX]
R560  33  [RES_0402]
R562  10K  [RES_0402]
R564  33  [RES_0402]
R565  33  [RES_0402]
R571  10K  [RES_0402]
R572  10K  [RES_0402]
R603  10K  [RES_0402]
R604  10K  [RES_0402]
R605  3.3K  [RES_0402]
R646  3.3K  [RES_0402]
TP21  Testpoint  [TP]
TP26  Testpoint  [TP]
TP27  Testpoint  [TP]
TP28  Testpoint  [TP]
TP29  Testpoint  [TP]
TP30  Testpoint  [TP]
TP31  Testpoint  [TP]
U504  TPD4E001  [SOIC6-DRL_TI]
U506  TPD4E001  [SOIC6-DRL_TI]
sheet PAGE20 - POWER & BYPASS CAPS
C526  10 uF  [CAP_0805]
C527  100 uF  [CAP_1206]
C528  0.1 uF  [CAP_0402]
C529  0.1 uF  [CAP_0402]
C530  0.1 uF  [CAP_0402]
C533  0.1 uF  [CAP_0402]
C534  0.1 uF  [CAP_0402]
C535  0.1 uF  [CAP_0402]
C536  0.1 uF  [CAP_0402]
C537  100 uF  [CAP_1206]
C538  10 uF  [CAP_0805]
C540  0.1 uF  [CAP_0402]
C541  0.1 uF  [CAP_0402]
C542  0.1 uF  [CAP_0402]
C543  0.1 uF  [CAP_0402]
C544  0.1 uF  [CAP_0402]
C553  0.1 uF  [CAP_0402]
C554  0.1 uF  [CAP_0402]
C555  0.1 uF  [CAP_0402]
C556  0.1 uF  [CAP_0402]
C557  0.1 uF  [CAP_0402]
C558  0.1 uF  [CAP_0402]
C559  0.1 uF  [CAP_0402]
C560  0.1 uF  [CAP_0402]
C561  0.1 uF  [CAP_0402]
C562  0.1 uF  [CAP_0402]
C563  0.1 uF  [CAP_0402]
C564  0.1 uF  [CAP_0402]
C565  0.1 uF  [CAP_0402]
C566  0.1 uF  [CAP_0402]
C567  0.1 uF  [CAP_0402]
C568  0.1 uF  [CAP_0402]
C569  0.1 uF  [CAP_0402]
C570  0.1 uF  [CAP_0402]
C571  0.1 uF  [CAP_0402]
C572  0.1 uF  [CAP_0402]
C575  10 uF  [CAP_0805]
C576  100 uF  [CAP_1206]
C577  10 uF  [CAP_0805]
C579  0.1 uF  [CAP_0402]
C580  0.1 uF  [CAP_0402]
C581  0.1 uF  [CAP_0402]
C582  0.1 uF  [CAP_0402]
C583  0.1 uF  [CAP_0402]
C584  0.1 uF  [CAP_0402]
C585  0.1 uF  [CAP_0402]
C586  0.1 uF  [CAP_0402]
C587  0.1 uF  [CAP_0402]
C588  0.1 uF  [CAP_0402]
C589  0.1 uF  [CAP_0402]
C590  0.1 uF  [CAP_0402]
C591  0.1 uF  [CAP_0402]
C592  0.1 uF  [CAP_0402]
C593  0.1 uF  [CAP_0402]
C594  0.1 uF  [CAP_0402]
C595  0.1 uF  [CAP_0402]
C596  0.1 uF  [CAP_0402]
C597  0.1 uF  [CAP_0402]
C598  0.1 uF  [CAP_0402]
C599  0.1 uF  [CAP_0402]
C600  0.1 uF  [CAP_0402]
C601  0.1 uF  [CAP_0402]
C602  0.1 uF  [CAP_0402]
C623  0.1 uF  [CAP_0402]
C624  0.1 uF  [CAP_0402]
C625  0.1 uF  [CAP_0402]
C626  0.1 uF  [CAP_0402]
C627  0.1 uF  [CAP_0402]
C628  0.1 uF  [CAP_0402]
C635  10 uF  [CAP_0805]
C636  10 uF  [CAP_0805]
C637  100 uF  [CAP_1206]
C638  10 uF  [CAP_0805]
FB500  470 Ohm  [FLTR_0603]
FB501  470 Ohm  [FLTR_0603]
FB502  470 Ohm  [FLTR_0603]
FB503  470 Ohm  [FLTR_0603]
FB504  470 Ohm  [FLTR_0603]
FB505  470 Ohm  [FLTR_0603]
FB506  470 Ohm  [FLTR_0603]
R536  0.36  [402]
R558  1.00  [402]
sheet PAGE21 - OUTPUT FMC CONNECTOR
J63  FMC 400POS CONN FEMALE  [CONN400-ASP-134486-01_SAM_MOD]  (sections A,B,C,D,E,F)

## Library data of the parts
C7 C8 C24 C25 C507 C514 C545 C546 = CAP_NP: Capacitor; MFG: AVX; Part Number: 08055C104MAT2A; RATING: 50V; SOURCE: DIGI 478-3351-1-ND; TOLERANCE: 20%; Type: X7R
C30 C515 C521 C528-C530 C533-C536 C539-C544 C553-C573 C579-C604 C623-C630 C640 C650 C651 C654 C659 C672 = CAP_NP: Capacitor; MFG: KEMET; Part Number: C0402C104K8RACTU; RATING: 10V; SOURCE: DIGI 399-3520-1-ND; TOLERANCE: 10%; Type: X7R
DN504 = DS_DUAL_CK_JAA_0: Diode, Schottky, Dual; DNI: DNI; MFG: STMICRO; Part Number: BAT54CFILM; RATING: 30V, 300mA; SOURCE: DIGI 497-3786-2-ND
J4 = CON4: Connector, USB type-B; MFG: MOLEX; Part Number: 67068-8000; SOURCE: DIGI WM17113-ND
J7 J16 = RS232: Connector, 9 pin, D-Sub; MFG: KYCON; Part Number: K20XHT-E9S-N; SOURCE: MOUSER 806-K20XHT-E9S-N
R18 R19 R29 R30 R532 R553 R584 R621 R671 R686 R689 R694 R722 = R: Resistor; ICA_MFR_NAME: PANASONIC; ICA_PARTNUM: $$1785048$$ERJ-3GSYJ102; MFG: PANASONIC; Part Number: ERJ-2GE0R00X; RATING: 1/10W; SOURCE: DIGI P0.0JCT-ND
R34 R534 R535 R562 R571-R573 R586 R603 R604 R684 R688 R690 R695 R704 R721 = R: Resistor; ICA_MFR_NAME: PANASONIC; ICA_PARTNUM: $$1785048$$ERJ-3GSYJ102; MFG: PANASONIC; Part Number: ERJ-2RKF1002X; RATING: 1/10W; SOURCE: DIGI P10.0KLCT-ND; TOLERANCE: 1%
R37-R40 R560 R564 R565 R674 R677-R679 = R: Resistor; ICA_MFR_NAME: PANASONIC; ICA_PARTNUM: $$1785048$$ERJ-3GSYJ102; MFG: PANASONIC; Part Number: ERJ-2GEJ330X; RATING: 1/10W; SOURCE: DIGI P33JCT-ND; TOLERANCE: 5%
R518 R519 = R: Resistor; ICA_MFR_NAME: PANASONIC; ICA_PARTNUM: $$1785048$$ERJ-3GSYJ102; MFG: VISHAY; Part Number: CRCW201022R0FKEF; RATING: 3/4W; TOLERANCE: 1%
R529 = R: Resistor; ICA_MFR_NAME: PANASONIC; ICA_PARTNUM: $$1785048$$ERJ-3GSYJ102; MFG: PANASONIC; Part Number: ERJ-3GEYJ223V; RATING: 1/10W; SOURCE: DIGI P22KGCT-ND; TOLERANCE: 5%
R530 R605 R646 R649 R672 R675 R676 R693 = R: Resistor; ICA_MFR_NAME: PANASONIC; ICA_PARTNUM: $$1785048$$ERJ-3GSYJ102; MFG: PANASONIC; Part Number: ERJ-2GEJ332X; RATING: 1/10W; SOURCE: DIGI P3.3KJCT-ND; TOLERANCE: 5%
R531 = R: Resistor; ICA_MFR_NAME: PANASONIC; ICA_PARTNUM: $$1785048$$ERJ-3GSYJ102; MFG: PANASONIC; Part Number: ERJ-3GEYJ152V; RATING: 1/10W; SOURCE: DIGI P1.5KGCT-ND; TOLERANCE: 5%
R533 R552 R623 R625 R682 R683 R685 R687 = R: Resistor; DNI: DNI; ICA_MFR_NAME: PANASONIC; ICA_PARTNUM: $$1785048$$ERJ-3GSYJ102; MFG: PANASONIC; Part Number: ERJ-2GE0R00X; RATING: 1/10W; SOURCE: DIGI P0.0JCT-ND
R619 R624 R680 = R: Resistor; DNI: DNI; ICA_MFR_NAME: PANASONIC; ICA_PARTNUM: $$1785048$$ERJ-3GSYJ102; MFG: PANASONIC; Part Number: ERJ-2GEJ330X; RATING: 1/10W; SOURCE: DIGI P33JCT-ND; TOLERANCE: 5%
TP21 TP26-TP31 TP34 TP37 TP38 TP41 TP44 TP46 TP48-TP58 TP64 = Testpoint: Test point
U6 U12 = MAX3232: IC, RS-232 Line Driver/Receiver; Part Number: SN75C3232EPWR; SOURCE: DIGI 296-13096-1-ND
U9 U10 = SN74LVC2G126: IC, Non-Inverting Buffer, Tri-State, Dual; MFG: TI; Part Number: SN74LVC2G126DCTR; SOURCE: DIGI 296-12554-1-ND
U11 = DDP442x: IC, ASIC; MFG: TI; SOURCE: PROVIDED BY TI
U502 = TPD4E1U06: IC, ESD Protection; MFG: TI; Part Number: TPD4E1U06DBVR; SOURCE: DIGI 296-35965-2-ND
U503 = 74LVC1G125_2: IC, Non-Inverting Buffer, Tri-State; MFG: TI; Part Number: SN74LVC1G125DBVR; SOURCE: DIGI 296-11603-1-ND
R585 R602 R642-R645 = R: Resistor; MFG: YAGEO; Part Number: RC0402FR-0722RL; RATING: 1/16W; SOURCE: DIGI 311-22.0LRTR-ND; TOLERANCE: 1%
R681 = R: Resistor; DNI: DNI; ICA_MFR_NAME: PANASONIC; ICA_PARTNUM: $$1785048$$ERJ-3GSYJ102; MFG: PANASONIC; Part Number: ERJ-2RKF1002X; RATING: 1/10W; SOURCE: DIGI P10.0KLCT-ND; TOLERANCE: 1%
U13 = SRAM_ALLIANCE: IC, SRAM; MFG: ALLIANCE; Part Number: AS6C8016-55ZIN; SOURCE: PROVIDED BY TI
U14 = FLASH_SPANSION: IC, Flash; MFG: ISSI; Part Number: IS29GL128-70SLET; SOURCE: PROVIDED BY TI
C644 = CAP_NP: Capacitor; MFG: KEMET; Part Number: C0805C105K4RACTU; RATING: 16V; SOURCE: DIGI 399-1284-2-ND; TOLERANCE: 10%; Type: X7R
C645 = CAP_NP: Capacitor; MFG: YAGEO; Part Number: CC0603KRX7R8BB103; RATING: 25V; TOLERANCE: 10%; Type: X7R
C648 C649 = CAP_NP: Capacitor; MFG: YAGEO; Part Number: CC0603KRX7R8BB104; RATING: 25V; SOURCE: DIGI PCC2277CT-ND; TOLERANCE: 10%; Type: X7R
J21 J29 J41 J44 = JUMPER-1x3: Jumper, 1x3; MFG: HARWIN; Part Number: M22-2510305; SOURCE: DIGI 952-1312-ND
J25 J26 = CON3: Connector, 3 pin; MFG: MOLEX; Part Number: 53398-0371; SOURCE: DIGI WM7607CT-ND
J54 = 12_HEADER: Connector; MFG: HIROSE; Part Number: FH12-12S-0.5SH(55); SOURCE: DIGI HFJ112TR-ND; Type: Flex
R596-R599 R738 R739 R758 R759 R761 = R: Resistor; MFG: PANASONIC; Part Number: ERJ-2GEJ330X; RATING: 1/10W; SOURCE: DIGI P33JCT-ND; TOLERANCE: 5%
R703 = R: Resistor; ICA_MFR_NAME: PANASONIC; ICA_PARTNUM: $$1785048$$ERJ-3GSYJ102; MFG: PANASONIC; Part Number: ERJ-6GEYJ111V; RATING: 1/8W; SOURCE: DIGI P110ACT-ND; TOLERANCE: 5%
R705 = R: Resistor; DNI: DNI; ICA_MFR_NAME: PANASONIC; ICA_PARTNUM: $$1785048$$ERJ-3GSYJ102; MFG: PANASONIC; Part Number: ERJ-2GEJ104X; RATING: 1/10W; SOURCE: DIGI P100KJCT-ND; TOLERANCE: 5%
R706 = R: Resistor; ICA_MFR_NAME: PANASONIC; ICA_PARTNUM: $$1785048$$ERJ-3GSYJ102; MFG: PANASONIC; Part Number: ERJ-3GEYJ222V; RATING: 1/10W; SOURCE: DIGI P2.2KGCT-ND; TOLERANCE: 5%
U512 = OPAMP_DUAL_4: IC, Comparator; MFG: TI; Part Number: LM393APWR; SOURCE: DIGI 296-6610-1-ND
J18 = CON22: Connector, 2x11 pin; MFG: JST; Part Number: B22B-PHDSS(LF)(SN); SOURCE: DIGI 455-1768-ND
J19 = CON20A: Connector, 20 pin; MFG: SAMTEC; Part Number: TSM-110-01-SM-DV; SOURCE: SAMTEC
J33 = CON12: Connector, 12 pin; MFG: MOLEX; Part Number: 53398-1271; SOURCE: DIGI WM7616CT-ND
J43 = CON6: Connector, 6 pin; MFG: MOLEX; Part Number: 53398-0671; SOURCE: DIGI WM7610CT-ND
R740 = R: Resistor; ICA_MFR_NAME: PANASONIC; ICA_PARTNUM: $$1785048$$ERJ-3GSYJ102; MFG: PANASONIC; Part Number: ERJ-2RKF1001X; RATING: 1/10W; SOURCE: DIGI P10.0KLCT-ND; TOLERANCE: 1%
RN500-RN503 = RPACK_4: Resistor Network; MFG: PANASONIC; Part Number: EXB-38V103JV; RATING: 1/16W; SOURCE: DIGI Y9103CT-ND; TOLERANCE: 5%
U8 U517 = SN74LVC827A: IC, 10 Ch Buffer; MFG: TI; Part Number: SN74LVC827APWR; SOURCE: DIGI 296-8548-1-ND
U513 = 74AUP1G79: IC, Non-inverting Flip-Flop; MFG: TI; Part Number: SN74AUP1G79DBVR
U516 = SN74LVC541ADGVR: IC, 8 Ch Buffer; MFG: TI
U523 = SN74LVC1G06_0: IC, Inverter; MFG: TI; Part Number: SN74LVC1G06DBVR; SOURCE: DIGI 296-8483-1-ND
J14 = CONN10: Connector, 10 pin; MFG: SAMTEC; Part Number: SQT-110-01-L-S-RA-003
J15 = CONN10: Connector, 10 pin; MFG: SAMTEC; Part Number: SQT-110-01-L-S-003
J24 = CON5: Connector, 5 pin; MFG: MOLEX; Part Number: 53398-0571; SOURCE: DIGI WM7609CT-ND
U504 U506 = TPD4E001: MFG: TI; Part Number: TPD4E001DRLR
C526 C538 C575 C577 C635 C636 C638 = CAP_NP: Capacitor; MFG: MURATA; Part Number: GRM21BR71A106KE51L; RATING: 10V; SOURCE: DIGI 490-3905-1-ND; TOLERANCE: 10%; Type: X7R
C527 C537 C576 C637 = CAP_NP: Capacitor; MFG: MURATA; Part Number: GRM31CR60J107ME39L; RATING: 6.3V; SOURCE: DIGI 490-4539-1-ND; TOLERANCE: 20%; Type: X7R
FB500-FB506 = INDUCTOR: Ferrite; ICA_MFR_NAME: STEWARD; ICA_PARTNUM: $$731362$$MI0603J680R-10; MFG: MURATA; Part Number: BLM18AG471SN1D; RATING: 500mA, 100MHz; SOURCE: DIGI 490-1013-1-ND
R536 = R: Resistor; MFG: TE CONNECTIVITY; Part Number: RLP73N1ER36FTDF; RATING: 1/8W; SOURCE: DIGI P.36AKCT-ND; TOLERANCE: 1%
R558 = R: Resistor; MFG: YAGEO; Part Number: RC0402FR-071RL; RATING: 1/16W; SOURCE: DIGI 311-1.00LRCT-ND; TOLERANCE: 1%
J63 = FMC_400POS_CONNECTOR: MFG: Samtec; PART NUMBER: ASP-134486-01

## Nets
GND: C7.2 C8.2 C24.2 C25.2 C30.1 C515.1 C521.1 C526.2 C527.2 C528.2 C529.2 C530.2 C533.2 C534.2 C535.2 C536.2 C537.2 C538.2 C539.1 C540.2 C541.2 C542.2 C543.2 C544.2 C553.2 C554.2 C555.2 C556.2 C557.2 C558.2 C559.2 C560.2 C561.2 C562.2 C563.2 C564.2 C565.2 C566.2 C567.2 C568.2 C569.2 C570.2 C571.2 C572.2 C573.1 C575.2 C576.2 C577.2 C579.2 C580.2 C581.2 C582.2 C583.2 C584.2 C585.2 C586.2 C587.2 C588.2 C589.2 C590.2 C591.2 C592.2 C593.2 C594.2 C595.2 C596.2 C597.2 C598.2 C599.2 C600.2 C601.2 C602.2 C603.1 C604.1 C623.2 C624.2 C625.2 C626.2 C627.2 C628.2 C629.1 C630.1 C635.2 C636.2 C637.2 C638.2 C640.1 C644.1 C645.1 C648.1 C649.1 C650.1 C651.1 C654.2 C659.1 C672.1 J4.4 J7.5(GND) J14.5 J15.5 J16.5(GND) J18.7 J18.10 J18.15 J18.16 J19.1 J19.16 J19.17 J19.18 J19.19 J19.20 J24.5 J25.3 J26.3 J33.1 J43.6 J54.3 J54.5 J54.7 J54.9 J54.11 J63.A01(GND) J63.A03(DP1_M2C_N) J63.A04(GND) J63.A05(GND) J63.A07(DP2_M2C_N) J63.A08(GND) J63.A09(GND) J63.A11(DP3_M2C_N) J63.A12(GND) J63.A13(GND) J63.A15(DP4_M2C_N) J63.A16(GND) J63.A17(GND) J63.A19(DP5_M2C_N) J63.A20(GND) J63.A21(GND) J63.A23(DP1_C2M_N) J63.A24(GND) J63.A25(GND) J63.A27(DP2_C2M_N) J63.A28(GND) J63.A29(GND) J63.A31(DP3_C2M_N) J63.A32(GND) J63.A33(GND) J63.A35(DP4_C2M_N) J63.A36(GND) J63.A37(GND) J63.A39(DP5_C2M_N) J63.A40(GND) J63.B02(GND) J63.B03(GND) J63.B05(DP9_M2C_N) J63.B06(GND) J63.B07(GND) J63.B09(DP8_M2C_N) J63.B10(GND) J63.B11(GND) J63.B13(DP7_M2C_N) J63.B14(GND) J63.B15(GND) J63.B17(DP6_M2C_N) J63.B18(GND) J63.B19(GND) J63.B22(GND) J63.B23(GND) J63.B25(DP9_C2M_N) J63.B26(GND) J63.B27(GND) J63.B29(DP8_C2M_N) J63.B30(GND) J63.B31(GND) J63.B33(DP7_C2M_N) J63.B34(GND) J63.B35(GND) J63.B37(DP6_C2M_N) J63.B38(GND) J63.B39(GND) J63.C01(GND) J63.C03(DP0_C2M_N) J63.C04(GND) J63.C05(GND) J63.C07(DP0_M2C_N) J63.C08(GND) J63.C09(GND) J63.C12(GND) J63.C13(GND) J63.C16(GND) J63.C17(GND) J63.C20(GND) J63.C21(GND) J63.C24(GND) J63.C25(GND) J63.C28(GND) J63.C29(GND) J63.C32(GND) J63.C33(GND) J63.C36(GND) J63.C38(GND) J63.C40(GND) J63.D02(GND) J63.D03(GND) J63.D06(GND) J63.D07(GND) J63.D10(GND) J63.D13(GND) J63.D16(GND) J63.D19(GND) J63.D22(GND) J63.D25(GND) J63.D28(GND) J63.D37(GND) J63.D39(GND) J63.E01(GND) J63.E04(GND) J63.E05(GND) J63.E08(GND) J63.E11(GND) J63.E14(GND) J63.E17(GND) J63.E20(GND) J63.E23(GND) J63.E26(GND) J63.E29(GND) J63.E32(GND) J63.E35(GND) J63.E38(GND) J63.E40(GND) J63.F02(GND) J63.F03(GND) J63.F06(GND) J63.F09(GND) J63.F12(GND) J63.F15(GND) J63.F18(GND) J63.F21(GND) J63.F24(GND) J63.F27(GND) J63.F30(GND) J63.F33(GND) J63.F36(GND) J63.F39(GND) J63.G01(GND) J63.G04(GND) J63.G05(GND) J63.G08(GND) J63.G11(GND) J63.G14(GND) J63.G17(GND) J63.G20(GND) J63.G23(GND) J63.G26(GND) J63.G29(GND) J63.G32(GND) J63.G35(GND) J63.G38(GND) J63.G40(GND) J63.H03(GND) J63.H06(GND) J63.H09(GND) J63.H12(GND) J63.H15(GND) J63.H18(GND) J63.H21(GND) J63.H24(GND) J63.H27(GND) J63.H30(GND) J63.H33(GND) J63.H36(GND) J63.H39(GND) J63.J01(GND) J63.J04(GND) J63.J05(GND) J63.J08(GND) J63.J11(GND) J63.J14(GND) J63.J17(GND) J63.J20(GND) J63.J23(GND) J63.J26(GND) J63.J29(GND) J63.J32(GND) J63.J35(GND) J63.J38(GND) J63.J40(GND) J63.K02(GND) J63.K03(GND) J63.K06(GND) J63.K09(GND) J63.K12(GND) J63.K15(GND) J63.K18(GND) J63.K21(GND) J63.K24(GND) J63.K27(GND) J63.K30(GND) J63.K33(GND) J63.K36(GND) J63.K39(GND) R529.1 R534.1 R562.1 R571.1 R572.1 R573.1 R603.1 R604.1 R605.1 R646.1 R683.2 R688.2 R690.2 R721.2 RN500.5 RN500.6 RN500.7 RN500.8 RN501.5 RN501.6 RN501.7 RN501.8 RN502.5 RN502.6 RN502.7 RN502.8 U6.15(GND) U8.1(~{OE1}) U8.12(GND) U8.13(~{OE2}) U9.4(GND) U10.4(GND) U11.A1(GND) U11.A2(GND) U11.A3(GND) U11.A17(L_VDQPAD_1) U11.A18(L_VDQPAD_3) U11.A24(GND) U11.A25(GND) U11.A26(GND) U11.AA6(GND) U11.AA9(GND) U11.AA12(GND) U11.AA15(GND) U11.AA18(GND) U11.AA21(GND) U11.AB5(GND) U11.AB14(VTEST1) U11.AB15(VTEST2) U11.AB16(R_VDQPAD_3) U11.AB17(R_VDQPAD_1) U11.AB22(GND) U11.AC4(GND) U11.AC17(R_VDQPAD_6) U11.AC18(R_VDQPAD_4) U11.AC23(GND) U11.AD3(GND) U11.AD17(R_VDQPAD_2) U11.AD18(R_VDQPAD_0) U11.AD24(GND) U11.AE3(GND) U11.AE17(R_VDQPAD_7) U11.AE24(GND) U11.AE25(GND) U11.AF1(GND) U11.AF2(GND) U11.AF3(GND) U11.AF17(R_VDQPAD_5) U11.AF24(GND) U11.AF25(GND) U11.AF26(GND) U11.B1(GND) U11.B2(GND) U11.B3(GND) U11.B17(L_VDQPAD_5) U11.B18(L_VDQPAD_7) U11.B25(GND) U11.C3(GND) U11.C18(L_VDQPAD_2) U11.C24(GND) U11.D4(GND) U11.D17(L_VDQPAD_0) U11.D18(L_VDQPAD_6) U11.D23(GND) U11.E5(GND) U11.E15(VTEST3) U11.E16(VTEST4) U11.E17(L_VDQPAD_4) U11.E22(GND) U11.F6(GND) U11.F9(GND) U11.F12(GND) U11.F15(GND) U11.F18(GND) U11.F21(GND) U11.G5(GND) U11.J5(GND) U11.J6(GND) U11.J21(GND) U11.K5(LVDS_AVS1) U11.K26(PLLD_VAS) U11.L5(GND) U11.L12(GND) U11.L13(GND) U11.L14(GND) U11.L15(GND) U11.L23(PLLD_VSS) U11.L25(PLLM1_VAS) U11.M6(GND) U11.M11(GND) U11.M12(GND) U11.M13(GND) U11.M14(GND) U11.M15(GND) U11.M16(GND) U11.M21(GND) U11.M22(PLLM1_VSS) U11.N5(GND) U11.N11(GND) U11.N12(GND) U11.N13(GND) U11.N14(GND) U11.N15(GND) U11.N16(GND) U11.P11(GND) U11.P12(GND) U11.P13(GND) U11.P14(GND) U11.P15(GND) U11.P16(GND) U11.P24(PLLM2_VSS) U11.R5(GND) U11.R6(GND) U11.R11(GND) U11.R12(GND) U11.R13(GND) U11.R14(GND) U11.R15(GND) U11.R16(GND) U11.R24(PLLS_VAS) U11.R26(PLLM2_VAS) U11.T12(GND) U11.T13(GND) U11.T14(GND) U11.T15(GND) U11.U5(GND) U11.V5(LVDS_AVS2) U11.V6(GND) U11.V21(GND) U11.W5(GND) U11.Y5(GND) U12.15(GND) U13.12(VSS) U13.34(VSS) U14.1(NC) U14.33(VSS) U14.52(VSS) U14.56(NC) U502.2(GND) U503.3(GND) U504.3(GND) U506.3(GND) U512.4(V-) U513.3(GND) U516.1(OE1) U516.7(A6) U516.8(A7) U516.9(A8) U516.10(GND) U516.19(OE2) U517.1(~{OE1}) U517.9(A8) U517.10(A9) U517.12(GND) U517.13(~{OE2}) U523.3 ; also on sheet 10 11 12 13 14 15 16 17 18 20 21
P5V: C672.2 J14.8 J15.8 J54.1 ; also on sheet 12 13 16 20 21
P12V: J18.2 J63.C35(12P0V) J63.C37(12P0V) ; also on sheet 13 14 15 16 17 21
3D_TOGGLE: U517.8(A7) ; also on sheet 12 13
A1P8V: R558.1 ; also on sheet 16
A_BLU_PWM: J18.5 J19.7 U8.21(Y3)
A_GRN_PWM: J18.3 J19.5 U8.22(Y2)
A_LED4_PWM: J18.9 J19.2 U8.20(Y4)
A_LED5_PWM: J18.11 J19.4 U8.19(Y5)
A_LED6_PWM: J18.13 J19.6 U8.18(Y6)
A_LED7_PWM: J18.17 J19.11 U8.17(Y7)
A_LED8_PWM: J18.19 J19.13 U8.16(Y8)
A_RED_PWM: J18.1 J19.3 U8.23(Y1)
A_SPARE_1: J18.18 J33.2 U517.23(Y1)
A_SPARE_2: J18.22 U8.15(Y9)
A_SPARE_3: J18.20 U8.14(Y10)
A_SSP0_CLK: R37.2 R38.2 R680.2 TP46.1 U11.AD4(SSP0_CLK)
A_SSP0_RXD: R625.1 R671.1 R672.1 U11.AD5(SSP0_RXD)
A_SSP0_TXD: R621.1 R623.1 U11.AB7(SSP0_TXD)
ADC_CSZ: J54.10 R597.1 TP64.1
ADC_RST/COMP_PWM: J54.2 R596.1 R694.2 TP55.1
ADC_SCLK: J54.4 R598.1 TP56.1
ADC_SDIN: J21.1 J54.6 TP57.1
ADC_SDO: J29.1 J54.8 TP58.1
BLU_LED_EN: RN500.3 U517.7(A6) ; also on sheet 12
BLU_PWM: RN501.2 U8.4(A3) U11.C20(GPIO_06)
COMP_SENSE_INPUT: J26.2 R704.1 U512.2(IN-)
COMP_SENSE_VDD: C649.2 J26.1 R703.1
COMP_SENSOR: J21.3 R705.1 R706.1 U512.1(OUT)
CSZ5_DAD2: J63.B28(DP8_C2M_P) ; also on sheet 18
DADADD0: J63.A14(DP4_M2C_P) ; also on sheet 18
DADADD1: J63.A18(DP5_M2C_P) ; also on sheet 18
DADADD2: J63.A22(DP1_C2M_P) ; also on sheet 18
DADADD3: J63.A26(DP2_C2M_P) ; also on sheet 18
DADINTZ: J63.B08(DP8_M2C_P) ; also on sheet 18
DADMD0: J63.A06(DP2_M2C_P) ; also on sheet 18
DADMD1: J63.A10(DP3_M2C_P) ; also on sheet 18
DADOEZ: J63.B04(DP9_M2C_P) ; also on sheet 18
DADSEL0: J63.A30(DP3_C2M_P) ; also on sheet 18
DADSEL1: J63.A34(DP4_C2M_P) ; also on sheet 18
DADSTB: J63.A38(DP5_C2M_P) ; also on sheet 18
DB/RED_PWM: RN500.4 U8.2(A1) ; also on sheet 12 13
DMDP3P3VA: J63.C39(3P3V) ; also on sheet 18
DMDP3P3VB: J63.D38(3P3V) ; also on sheet 18
DMDSPARE0: J63.B16(DP6_M2C_P) ; also on sheet 18
DRV_RST/SSP2_CSZ_1: U516.6(A5) ; also on sheet 12
EXT_ARSTZ: J63.A02(DP1_M2C_P) ; also on sheet 13 17 20
FLASH_A19_A21: R687.2 R689.2 U14.11(A19)
FLASH_A21_VPP: R685.1 R686.2 U14.15(A21)
FLASH_CSSZ: R585.2 U14.32(CE#)
FLASH_CSZ: R585.1 U11.E12(PM_CSZ_1)
FLASH_RSTZ: R552.1 R553.1 U14.14(RESET#)
FREQ_SENSOR: J25.2 J29.3
GPIO_21: RN503.3 U8.10(A9) U11.E20(GPIO_21)
GPIO_23: RN503.4 U8.11(A10) U11.E21(GPIO_23)
GPIO_30: R564.2 U11.D25(GPIO_30)
GPIO_32: R565.2 U11.E24(GPIO_32)
GPIO_33: R560.2 U11.D26(GPIO_33)
GPIO_54: RN502.4 U517.2(A1) ; also on sheet 12
GPIO_74: J21.2 U11.AE10(GPIO_74)
GPIO_75: J29.2 R599.1
GPIO_81: J24.4 U11.AB10(GPIO_81)
GRN_LED_EN: RN500.2 U517.6(A5) ; also on sheet 12
GRN_PWM: RN501.1 U8.3(A2) U11.B20(GPIO_05)
LAMPLITZ: J33.4 ; also on sheet 12
LED4_PWM: RN501.3 U8.5(A4) U11.A20(GPIO_07)
LED5_PWM: RN501.4 U8.6(A5) U11.A21(GPIO_08)
LED6_PWM: RN502.1 U8.7(A6) U11.B21(GPIO_09)
LED7_PWM: RN502.2 U8.8(A7) U11.A22(GPIO_10)
LED8_PWM: RN502.3 U8.9(A8) U11.A23(GPIO_11)
LED_DIN: J43.2 J44.3 R721.1 R722.2 TP50.1
LED_DIR: J43.5 R739.2 TP51.1
LED_DOUT: J43.3 R759.2 TP53.1
LED_EN: J33.3 J41.2
LED_OE: J43.4 R761.2 TP52.1
LED_SCLK: J43.1 R758.2 TP54.1
LMPCTRL: U517.3(A2) ; also on sheet 12
M_DCLKA_N: J63.K05(CLK2_M2C_N) ; also on sheet 18
M_DCLKA_P: J63.K04(CLK2_M2C_P) ; also on sheet 18
M_DCLKB_N: J63.J03(CLK3_M2C_N) ; also on sheet 18
M_DCLKB_P: J63.J02(CLK3_M2C_P) ; also on sheet 18
M_DDA00_N: J63.D21(LA17_N_CC) ; also on sheet 18
M_DDA00_P: J63.D20(LA17_P_CC) ; also on sheet 18
M_DDA01_N: J63.C23(LA18_N_CC) ; also on sheet 18
M_DDA01_P: J63.C22(LA18_P_CC) ; also on sheet 18
M_DDA02_N: J63.H23(LA19_N) ; also on sheet 18
M_DDA02_P: J63.H22(LA19_P) ; also on sheet 18
M_DDA03_N: J63.G22(LA20_N) ; also on sheet 18
M_DDA03_P: J63.G21(LA20_P) ; also on sheet 18
M_DDA04_N: J63.H26(LA21_N) ; also on sheet 18
M_DDA04_P: J63.H25(LA21_P) ; also on sheet 18
M_DDA05_N: J63.G25(LA22_N) ; also on sheet 18
M_DDA05_P: J63.G24(LA22_P) ; also on sheet 18
M_DDA06_N: J63.D24(LA23_N) ; also on sheet 18
M_DDA06_P: J63.D23(LA23_P) ; also on sheet 18
M_DDA07_N: J63.H29(LA24_N) ; also on sheet 18
M_DDA07_P: J63.H28(LA24_P) ; also on sheet 18
M_DDA08_N: J63.G28(LA25_N) ; also on sheet 18
M_DDA08_P: J63.G27(LA25_P) ; also on sheet 18
M_DDA09_N: J63.D27(LA26_N) ; also on sheet 18
M_DDA09_P: J63.D26(LA26_P) ; also on sheet 18
M_DDA10_N: J63.C27(LA27_N) ; also on sheet 18
M_DDA10_P: J63.C26(LA27_P) ; also on sheet 18
M_DDA11_N: J63.H32(LA28_N) ; also on sheet 18
M_DDA11_P: J63.H31(LA28_P) ; also on sheet 18
M_DDA12_N: J63.G31(LA29_N) ; also on sheet 18
M_DDA12_P: J63.G30(LA29_P) ; also on sheet 18
M_DDA13_N: J63.H35(LA30_N) ; also on sheet 18
M_DDA13_P: J63.H34(LA30_P) ; also on sheet 18
M_DDA14_N: J63.G34(LA31_N) ; also on sheet 18
M_DDA14_P: J63.G33(LA31_P) ; also on sheet 18
M_DDA15_N: J63.H38(LA32_N) ; also on sheet 18
M_DDA15_P: J63.H37(LA32_P) ; also on sheet 18
M_DDB00_N: J63.K26(HB00_CC_N) ; also on sheet 18
M_DDB00_P: J63.K25(HB00_CC_P) ; also on sheet 18
M_DDB01_N: J63.J25(HB01_N) ; also on sheet 18
M_DDB01_P: J63.J24(HB01_P) ; also on sheet 18
M_DDB02_N: J63.F23(HB02_N) ; also on sheet 18
M_DDB02_P: J63.F22(HB02_P) ; also on sheet 18
M_DDB03_N: J63.E22(HB03_N) ; also on sheet 18
M_DDB03_P: J63.E21(HB03_P) ; also on sheet 18
M_DDB04_N: J63.F26(HB04_N) ; also on sheet 18
M_DDB04_P: J63.F25(HB04_P) ; also on sheet 18
M_DDB05_N: J63.E25(HB05_N) ; also on sheet 18
M_DDB05_P: J63.E24(HB05_P) ; also on sheet 18
M_DDB06_N: J63.K29(HB06_N_CC) ; also on sheet 18
M_DDB06_P: J63.K28(HB06_P_CC) ; also on sheet 18
M_DDB07_N: J63.J28(HB07_N) ; also on sheet 18
M_DDB07_P: J63.J27(HB07_P) ; also on sheet 18
M_DDB08_N: J63.F29(HB08_N) ; also on sheet 18
M_DDB08_P: J63.F28(HB08_P) ; also on sheet 18
M_DDB09_N: J63.E28(HB09_N) ; also on sheet 18
M_DDB09_P: J63.E27(HB09_P) ; also on sheet 18
M_DDB10_N: J63.K32(HB10_N) ; also on sheet 18
M_DDB10_P: J63.K31(HB10_P) ; also on sheet 18
M_DDB11_N: J63.J31(HB11_N) ; also on sheet 18
M_DDB11_P: J63.J30(HB11_P) ; also on sheet 18
M_DDB12_N: J63.F32(HB12_N) ; also on sheet 18
M_DDB12_P: J63.F31(HB12_P) ; also on sheet 18
M_DDB13_N: J63.E31(HB13_N) ; also on sheet 18
M_DDB13_P: J63.E30(HB13_P) ; also on sheet 18
M_DDB14_N: J63.K35(HB14_N) ; also on sheet 18
M_DDB14_P: J63.K34(HB14_P) ; also on sheet 18
M_DDB15_N: J63.J34(HB15_N) ; also on sheet 18
M_DDB15_P: J63.J33(HB15_P) ; also on sheet 18
M_SCTRLA_N: J63.G37(LA33_N) ; also on sheet 18
M_SCTRLA_P: J63.G36(LA33_P) ; also on sheet 18
M_SCTRLB_N: J63.F35(HB16_N) ; also on sheet 18
M_SCTRLB_P: J63.F34(HB16_P) ; also on sheet 18
MODEB: J63.B12(DP7_M2C_P) ; also on sheet 18
P1P1V: C544.1 C553.1 C554.1 C557.1 C558.1 C559.1 C561.1 C563.1 C565.1 C566.1 C569.1 C571.1 C575.1 C576.1 C579.1 C581.1 C583.1 C586.1 C588.1 C590.1 C593.1 C594.1 C596.1 C599.1 C601.1 C602.1 C635.1 R536.1 U11.AA8(VDDC) U11.AA11(VDDC) U11.AA14(VDDC) U11.AA17(VDDC) U11.AA20(VDDC) U11.F7(VDDC) U11.F10(VDDC) U11.F13(VDDC) U11.F16(VDDC) U11.F19(VDDC) U11.G21(VDDC) U11.H6(VDDC) U11.K21(VDDC) U11.L6(VDDC) U11.L11(VDDC) U11.L16(VDDC) U11.N21(VDDC) U11.P6(VDDC) U11.T11(VDDC) U11.T16(VDDC) U11.T21(VDDC) U11.U6(VDDC) U11.W21(VDDC) U11.Y6(VDDC) ; also on sheet 15 16
P1P8V: C542.1 C560.1 C567.1 C572.1 C584.1 C585.1 C587.1 C589.1 C591.1 C592.1 C595.1 C600.1 C623.1 C624.1 C625.1 C626.1 C627.1 C628.1 C636.1 C637.1 C638.1 U11.AA5(LVDSAVD) U11.AA13(DRAMVDD) U11.AE1(LVDSAVD) U11.C1(LVDSAVD) U11.F5(LVDSAVD) U11.F14(DRAMVDD) U11.G6(LVDSAVD) U11.H5(DRAMVDD) U11.H21(DRAMVDD) U11.K6(LVDSAVD) U11.M5(LVDSAVD) U11.N6(DRAMVDD) U11.P5(LVDSAVD) U11.P21(DRAMVDD) U11.T5(LVDSAVD) U11.T6(DRAMVDD) U11.U21(DRAMVDD) U11.W6(LVDSAVD) ; also on sheet 15 16
P3P3V: C30.2 C515.2 C521.2 C526.1 C538.1 C540.1 C555.1 C556.1 C562.1 C564.1 C568.1 C570.1 C573.2 C577.1 C580.1 C582.1 C597.1 C598.1 C603.2 C604.2 C629.2 C630.2 C648.2 C650.2 C651.2 C654.1 C659.2 DN504.3 J24.1 J25.1 R34.2 R530.2 R533.2 R584.1 R586.1 R649.2 R672.2 R675.2 R676.2 R681.1 R684.1 R685.2 R693.2 R703.2 R704.2 R706.2 R740.2 RN503.5 RN503.6 RN503.7 RN503.8 U8.24(VCC) U11.AA7(VDD33) U11.AA10(VDD33) U11.AA16(VDD33) U11.AA19(VDD33) U11.AE26(CFO_VDD33) U11.F8(VDD33) U11.F11(VDD33) U11.F17(VDD33) U11.F20(VDD33) U11.L21(VDD33) U11.R21(VDD33) U11.Y21(VDD33) U12.16(VCC) U13.11(VCC) U13.33(VCC) U14.43(VCC) U503.5(VCC) U504.6(VCC) U506.6(VCC) U512.8(V+) U513.5(VCC) U516.20(Vcc) U517.24(VCC) U523.5 ; also on sheet 10 11 12 13 14 15 16 17 18 20 21
P3P3V_LP: C539.2 C640.2 R532.2 R535.2 ; also on sheet 11 15 16 17
PACKET_RDY: J14.9 J15.9 R603.2 TP30.1 U11.F25(GPIO_57) U506.2(IO2)
PB_INDEX: J14.10 J15.10 J24.2 R605.2 TP21.1 U11.AE9(GPIO_79) U506.1(IO1)
PB_IR_ENABLE: J24.3 U11.AD9(GPIO_80)
PLLD_VAD: C535.1 FB506.2 U11.K25(PLLD_VAD)
PLLD_VDD: C543.1 FB503.2 U11.L22(PLLD_VDD)
PLLM1_VAD: C534.1 FB505.2 U11.L24(PLLM1_VAD)
PLLM1_VDD: C533.1 FB504.2 U11.L26(PLLM1_VDD)
PLLM2_VAD: C530.1 FB501.2 U11.R25(PLLM2_VAD)
PLLM2_VDD: C541.1 FB502.2 U11.P23(PLLM2_VDD)
PLLS_VAD: C529.1 FB500.2 U11.R23(PLLS_VAD)
PLUG_DETECT: J14.7 J15.7 R646.2 TP31.1 U11.F23(GPIO_34) U506.5(IO4)
PM_ADR_0: U11.C7(PM_ADDR_00) U13.5(A0) U14.31(A0)
PM_ADR_1: U11.A7(PM_ADDR_01) U13.4(A1) U14.26(A1)
PM_ADR_2: U11.B7(PM_ADDR_02) U13.3(A2) U14.25(A2)
PM_ADR_3: U11.C8(PM_ADDR_03) U13.2(A3) U14.24(A3)
PM_ADR_4: U11.D8(PM_ADDR_04) U13.1(A4) U14.23(A4)
PM_ADR_5: U11.A8(PM_ADDR_05) U13.44(A5) U14.22(A5)
PM_ADR_6: U11.B8(PM_ADDR_06) U13.43(A6) U14.21(A6)
PM_ADR_7: U11.C9(PM_ADDR_07) U13.42(A7) U14.20(A7)
PM_ADR_8: U11.D9(PM_ADDR_08) U13.28(A8) U14.10(A8)
PM_ADR_9: U11.E9(PM_ADDR_09) U13.27(A9) U14.9(A9)
PM_ADR_10: U11.A9(PM_ADDR_10) U13.26(A10) U14.8(A10)
PM_ADR_11: U11.B9(PM_ADDR_11) U13.25(A11) U14.7(A11)
PM_ADR_12: U11.C10(PM_ADDR_12) U13.24(A12) U14.6(A12)
PM_ADR_13: U11.D10(PM_ADDR_13) U13.23(A13) U14.5(A13)
PM_ADR_14: U11.E10(PM_ADDR_14) U13.22(A14) U14.4(A14)
PM_ADR_15: U11.C11(PM_ADDR_15) U13.21(A15) U14.3(A15)
PM_ADR_16: U11.D11(PM_ADDR_16) U13.20(A16) U14.54(A16)
PM_ADR_17: U11.A11(PM_ADDR_17) U13.19(A17) U14.19(A17)
PM_ADR_18: U11.B11(PM_ADDR_18) U13.18(A18) U14.18(A18)
PM_ADR_19: R682.1 R689.1 U11.C12(PM_ADDR_19)
PM_ADR_20: U11.D12(PM_ADDR_20) U14.12(A20)
PM_ADR_21: R686.1 R687.1 R688.1 U11.E11(GPIO_35)
PM_ADR_22: R690.1 U11.A12(GPIO_36) U14.2(A22)
PM_BLS0: R643.1 U11.A6(PM_BLSZ_0)
PM_BLS0S: R643.2 U13.39(LB#)
PM_BLS1: R644.1 U11.B6(PM_BLSZ_1)
PM_BLS1S: R644.2 U13.40(UB#)
PM_DAT_0: U11.B13(PM_DATA_00) U13.7(DQ_0) U14.35(DQ0)
PM_DAT_1: U11.C14(PM_DATA_01) U13.8(DQ_1) U14.37(DQ1)
PM_DAT_2: U11.D14(PM_DATA_02) U13.9(DQ_2) U14.39(DQ2)
PM_DAT_3: U11.E13(PM_DATA_03) U13.10(DQ_3) U14.41(DQ3)
PM_DAT_4: U11.A14(PM_DATA_04) U13.13(DQ_4) U14.44(DQ4)
PM_DAT_5: U11.B14(PM_DATA_05) U13.14(DQ_5) U14.46(DQ5)
PM_DAT_6: U11.C15(PM_DATA_06) U13.15(DQ_6) U14.48(DQ6)
PM_DAT_7: U11.D15(PM_DATA_07) U13.16(DQ_7) U14.50(DQ7)
PM_DAT_8: U11.E14(PM_DATA_08) U13.29(DQ_8) U14.36(DQ8)
PM_DAT_9: U11.C16(PM_DATA_09) U13.30(DQ_9) U14.38(DQ9)
PM_DAT_10: U11.D16(PM_DATA_10) U13.31(DQ_10) U14.40(DQ10)
PM_DAT_11: U11.B15(PM_DATA_11) U13.32(DQ_11) U14.42(DQ11)
PM_DAT_12: U11.A15(PM_DATA_12) U13.35(DQ_12) U14.45(DQ12)
PM_DAT_13: U11.A16(PM_DATA_13) U13.36(DQ_13) U14.47(DQ13)
PM_DAT_14: U11.B16(PM_DATA_14) U13.37(DQ_14) U14.49(DQ14)
PM_DAT_15: U11.C17(PM_DATA_15) U13.38(DQ_15) U14.51(DQ15)
PM_OESZ: R645.2 U13.41(OE#) U14.34(OE#)
PM_OEZ: R645.1 U11.C13(PM_OEZ)
PM_SRAM_CSSZ: R642.2 U13.6(CE#)
PM_SRAM_CSZ: R642.1 U11.D13(PM_CSZ_0)
PM_WESZ: R602.2 U13.17(WE#) U14.13(WE#)
PM_WEZ: R602.1 U11.B12(PM_WEZ)
POSENSE: R553.2 ; also on sheet 15 17
PWRGOOD: R552.2 U9.1(1OE) U9.7(2OE) U10.1(1OE) U10.7(2OE) ; also on sheet 10 11 12 15 17
RED_LED_EN: RN500.1 U517.5(A4) ; also on sheet 12
SENSE_PULSE: RN503.1 U11.G25(GPIO_58) U517.11(A10)
SENSE_PULSE_BUF: J18.12 J19.8 J33.12 U517.14(Y10)
SSI_3D_TOGGLE: J18.14 J19.15 J33.9 U517.17(Y7)
SSI_STB_B: J18.8 J19.14 J33.8 U517.18(Y6)
SSI_STB_G: J18.6 J19.12 J33.7 U517.19(Y5)
SSI_STB_R: J18.4 J19.10 J33.6 U517.20(Y4)
SSI_SUBFRAME: J18.21 J19.9 J33.5 U517.21(Y3)
SSP0_CLK: R38.1 ; also on sheet 15 17
SSP0_CLK_DMD: J63.B32(DP7_C2M_P) R37.1
SSP0_CLK_DUAL: R680.1 ; also on sheet 20
SSP0_CSZ0: R676.1 R677.2 TP44.1 U11.AC5(SSP0_CSZ_0)
SSP0_CSZ0_DAD1: J63.B24(DP9_C2M_P) R677.1
SSP0_CSZ1: R674.2 R675.1 TP37.1 U11.AB6(SSP0_CSZ_1)
SSP0_CSZ1_DMD: J63.C06(DP0_M2C_P) R674.1
SSP0_CSZ2: R649.1 R679.2 TP41.1 U11.AC3(SSP0_CSZ_2)
SSP0_CSZ2_PMD1: R679.1 ; also on sheet 17
SSP0_CSZ3: R678.2 R693.1 TP34.1 U11.AB4(GPIO_27)
SSP0_CSZ3_PMD2: R678.1 ; also on sheet 15
SSP0_RXD: J63.B36(DP6_C2M_P) R623.2 R624.2 R671.2 TP49.1 ; also on sheet 15 17 18
SSP0_RXD_DUAL: R624.1 ; also on sheet 20
SSP0_TXD: R40.1 ; also on sheet 15 17
SSP0_TXD_DMD: J63.C02(DP0_C2M_P) R39.1
SSP0_TXD_DUAL: R619.1 ; also on sheet 20
SSP1_CLK: J14.6 J15.6 R564.1 R572.2 TP26.1 U504.5(IO4)
SSP1_CSZ0: J14.1 J15.1 R560.1 R562.2 TP29.1 U504.1(IO1)
SSP1_DI: J14.2 J15.2 R604.2 TP28.1 U11.F22(GPIO_31) U504.4(IO3)
SSP1_DO: J14.4 J15.4 R565.1 R571.2 TP27.1 U504.2(IO2)
SSP2/LED_DIN: R722.1 U513.1(D)
SSP2_CLK: U516.2(A1) U516.3(A2) ; also on sheet 12
SSP2_CSZ_0: U516.5(A4) ; also on sheet 12
SSP2_DIN: J44.2 ; also on sheet 12
SSP2_DO: U516.4(A3) ; also on sheet 12
SUBFRAME: RN503.2 U11.D22(GPIO_22) U517.4(A3)
UART0_CTSZ: U6.12(R1OUT) U9.2(1A)
UART0_CTSZ_BUF: U9.6(1Y) U11.AE2(UART0_CTSZ)
UART0_CTSZ_CON: J7.7(RTS) U6.13(R1IN)
UART0_DCD_CON: J7.1(DCD) R18.1
UART0_DSR_CON: J7.6(DSR) R18.2 R19.2
UART0_DTR_CON: J7.4(DTR) R19.1
UART0_RSTZ_CON: J7.8(CTS) U6.14(T1OUT)
UART0_RTSZ: U10.5(2A) U11.AD2(UART0_RTSZ)
UART0_RTSZ_BUF: R534.2 U6.11(T1IN) U10.3(2Y) ; also on sheet 17
UART0_RXD: U6.9(R2OUT) U9.5(2A) ; also on sheet 17
UART0_RXD_BUF: U9.3(2Y) U11.AD1(UART0_RXD)
UART0_RXD_CON: J7.3(TD) U6.8(R2IN)
UART0_TXD: U10.2(1A) U11.AB3(UART0_TXD)
UART0_TXD_BUF: R535.1 U6.10(T2IN) U10.6(1Y)
UART0_TXD_CON: J7.2(RD) U6.7(T2OUT)
UART1_CTSZ: U12.12(R1OUT) ; also on sheet 12
UART1_CTSZ_CON: J16.7(RTS) U12.13(R1IN)
UART1_DCD_CON: J16.1(DCD) R29.1
UART1_DSR_CON: J16.6(DSR) R29.2 R30.2
UART1_DTR_CON: J16.4(DTR) R30.1
UART1_RSTZ_CON: J16.8(CTS) U12.14(T1OUT)
UART1_RTSZ: R573.2 U12.11(T1IN) ; also on sheet 12
UART1_RXD: U12.9(R2OUT) ; also on sheet 12 21
UART1_RXD_CON: J16.3(TD) U12.8(R2IN)
UART1_TXD: R34.1 U12.10(T2IN) ; also on sheet 12 21
UART1_TXD_CON: J16.2(RD) U12.7(T2OUT)
USB_DAT_N: J4.2 R518.1 U502.6(D1-)
USB_DAT_NS: DN504.1 R518.2 U11.C5(USB_DAT_N)
USB_DAT_P: J4.3 R519.1 R531.1 U502.1(D1+)
USB_DAT_PS: DN504.2 R519.2 U11.D6(USB_DAT_P)
USB_ENZ: R530.1 U503.1(~{OE}) ; also on sheet 12
N16906053: C24.1 U12.6(V-)
N16906057: C546.2 U12.1(C1+)
N16906061: C546.1 U12.3(C1-)
N16906093: C545.2 U12.4(C2+)
N16906098: C545.1 U12.5(C2-)
N16906262: R532.1 R533.1 U6.16(VCC) U9.8(VCC) U10.8(VCC)
N16906414: R39.2 R40.2 R619.2 R621.2 R625.2 TP48.1
N16906499: C8.1 U6.2(V+)
N16906505: J4.1 R529.2 U503.2(I)
N16906696: C7.1 U6.6(V-)
N16906819: C514.2 U6.1(C1+)
N16906911: C514.1 U6.3(C1-)
N16906913: R531.2 U503.4(O)
N16907106: C507.2 U6.4(C2+)
N16907207: C507.1 U6.5(C2-)
N16910878: R586.2 U14.53(BYTE#)
N16910921: R683.1 R684.2 U14.16(WP#/ACC)
N16911179: R584.2 U14.29(VIO)
N16911537: R681.2 U14.27(NC)
N16912987: R682.2 U14.17(RY/BY#)
N17126992: R597.2 U11.AC10(GPIO_76)
N17126998: R598.2 U11.AF10(GPIO_73)
N17172867: R599.2 U11.AD10(GPIO_75)
N17173381: C644.2 R695.1 R705.2 TP38.1 U512.3(IN+)
N17173524: C645.2 R694.1 R695.2
N17223452: C527.1 C528.1 FB500.1 FB502.1 FB503.1 FB504.1 R536.2
N17234365: C536.1 C537.1 FB501.1 FB505.1 FB506.1 R558.2
N17386710: R596.2 U11.AB11(GPIO_77)
N17418086: J41.3 U517.22(Y2) U523.2
N17418532: J33.10 U517.16(Y8)
N17418535: J33.11 U517.15(Y9)
N17423586: J41.1 R740.1 U523.4
N17436039: C25.1 U12.2(V+)
N18108465: R738.2 U513.2(CLK)
N18206464: R758.1 U516.18(Y1)
N18206467: R738.1 U516.17(Y2)
N18206470: R759.1 U516.16(Y3)
N18206473: R761.1 U516.15(Y4)
N18206476: R739.1 U516.14(Y5)
N18206999: J44.1 U513.4(Q)

Not connected (* = marked no-connect by the designer): J7 9(RING)*; J14 3*; J15 3*; J16 9(RING)*; J54 12*; J63 B01(RES1)* B20(GBTCLK1_M2C_P)* B21(GBTCLK1_M2C_N)* B40(RES0)* C10(LA06_P)* C11(LA06_N)* C14(LA10_P)* C15(LA10_N)* C18(LA14_P)* C19(LA14_N)* C30(SCL)* C31(SDA)* C34(GA0)* D01(PG_C2M)* D04(GBTCLK0_M2C_P)* D05(GBTCLK0_M2C_N)* D08(LA01_P_CC)* D09(LA01_N_CC)* D11(LA05_P)* D12(LA05_N)* D14(LA09_P)* D15(LA09_N)* D17(LA13_P)* D18(LA13_N)* D29(TCK)* D30(TDI)* D31(TDO)* D32(3P3VAUX)* D33(TMS)* D34(TRST_L)* D35(GA1)* D36(3P3V)* D40(3P3V)* E02(HA01_P_CC)* E03(HA01_N_CC)* E06(HA05_P)* E07(HA05_N)* E09(HA09_P)* E10(HA09_N)* E12(HA13_P)* E13(HA13_N)* E15(HA16_P)* E16(HA16_N)* E18(HA20_P)* E19(HA20_N)* E33(HB19_P)* E34(HB19_N)* E36(HB21_P)* E37(HB21_N)* E39(VADJ)* F01(PG_M2C)* F04(HA00_P_CC)* F05(HA00_N_CC)* F07(HA04_P)* F08(HA04_N)* F10(HA08_P)* F11(HA08_N)* F13(HA12_P)* F14(HA12_N)* F16(HA15_P)* F17(HA15_N)* F19(HA19_P)* F20(HA19_N)* F37(HB20_P)* F38(HB20_N)* F40(VADJ)* G02(CLK1_M2C_P)* G03(CLK1_M2C_N)* G06(LA00_P_CC)* G07(LA00_N_CC)* G09(LA03_P)* G10(LA03_N)* G12(LA08_P)* G13(LA08_N)* G15(LA12_P)* G16(LA12_N)* G18(LA16_P)* G19(LA16_N)* G39(VADJ)* H01(VREF_A_M2C)* H02(PRSNT_M2C_L)* H04(CLK0_M2C_P)* H05(CLK0_M2C_N)* H07(LA02_P)* H08(LA02_N)* H10(LA04_P)* H11(LA04_N)* H13(LA07_P)* H14(LA07_N)* H16(LA11_P)* H17(LA11_N)* H19(LA15_P)* H20(LA15_N)* H40(VADJ)* J06(HA03_P)* J07(HA03_N)* J09(HA07_P)* J10(HA07_N)* J12(HA11_P)* J13(HA11_N)* J15(HA14_P)* J16(HA14_N)* J18(HA18_P)* J19(HA18_N)* J21(HA22_P)* J22(HA22_N)* J36(HB18_P)* J37(HB18_N)* J39(VIO_B_M2C)* K01(VREF_B_M2C)* K07(HA02_P)* K08(HA02_N)* K10(HA06_P)* K11(HA06_N)* K13(HA10_P)* K14(HA10_N)* K16(HA17_P_CC)* K17(HA17_N_CC)* K19(HA21_P)* K20(HA21_N)* K22(HA23_P)* K23(HA23_N)* K37(HB17_P_CC)* K38(HB17_N_CC)* K40(VIO_B_M2C)*; U11 A13(PM_CSZ_2)*; U14 28(NC)* 30(NC)* 55(NC)*; U502 3(D2+)* 4(D2-)* 5(NC)*; U506 4(IO3)*; U516 11(Y8)* 12(Y7)* 13(Y6)*; U523 1*

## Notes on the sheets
sheet 1
- Secondary Controller Bus A
- Secondary Controller Bus B
- Main Controller Bus B
- Main Controller Bus A
- Max Power Transfer (pins):
  1A at 12V
- FMC TO DMD
sheet 2
- (C) COPYRIGHT 2023
         Texas Instruments
        All Rights Reserved
sheet 3
- Rev A
- Initial Release
- Rev B
- -Replaced J500 with J63 (FMC connector)
  -Updated Controller Bus Names from DDX_P/N with M_DDX_P/N
- REVISION HISTORY
- (C) COPYRIGHT 2023
         Texas Instruments
        All Rights Reserved
sheet 4
- DLPC4430 P1P1V Bypass Capacitors
- DLPC4430 P1P8V LVDS Bypass Capacitors
- DLPC4430 P1P8V DRAM Bypass Capacitors
- DLPC4430 P3P3V Bypass Capacitors
- (C) COPYRIGHT 2023
         Texas Instruments
        All Rights Reserved
- DLPC4430 Power and Bypass Capacitors
- (C) COPYRIGHT 2023
         Texas Instruments
        All Rights Reserved
sheet 5
- Note: Only one connector is needed for
  production designs (J14 or J15)
- PointBlank Interface
- (C) COPYRIGHT 2023
         Texas Instruments
        All Rights Reserved
sheet 6
- PWM SSI DRIVER I/F
- SPI DRIVER AND CONTROL I/F
- PULL-UP/PULL-DOWN RESISTORS
- J48
  Jumper Pins 1 & 2: DLPC4430 with OSRAM Driver
  Jumper Pins 2 & 3: Default
- TESTPOINTS
- Note: U513 is needed to read
  from an OSRAM driver for
  DLPC4430
- SSI Driver Interfaces
- (C) COPYRIGHT 2023
         Texas Instruments
        All Rights Reserved
sheet 7
- COMPARATOR SENSOR I/F
- ADC INTEGRATING SENSOR BOARD I/F
- LIGHT TO FREQUENCY SENSOR I/F
- SSI SENSOR INTERFACE
- (C) COPYRIGHT 2023
         Texas Instruments
        All Rights Reserved
sheet 8
- Note:
  TI reference design supports both
  TSOPII-48 and TSOPII-56 Flash types.
  The reference design uses a TSOPII-48
  Flash part. Please refer to diagram
  below for pinout and footprint
  comparison.
- 1
- 56
- 2
- 55
- 3
- 1
- 48
- 54
- 4
- 2
- 47
- 53
- 5
- 3
- 46
- 52
- 6
- 7
- 4
- 5
- 44
- 45
- 50
- 51
- 8
- 6
- 43
- 49
- 9
- 7
- 42
- 48
- 10
- 8
- 41
- 47
- 11
- 9
- 40
- 46
- 12
- 13
- 10
- 11
- 38
- 39
- 44
- 45
- 14
- 12
- 37
- 43
- 15
- 13
- 36
- 42
- 16
- 14
- 35
- 41
- 17
- 15
- 34
- 40
- 18
- 16
- 33
- 39
- 19
- 20
- 17
- 18
- 31
- 32
- 37
- 38
- 21
- 19
- 30
- 36
- 22
- 20
- 29
- 35
- 23
- 21
- 28
- 34
- 24
- 22
- 27
- 33
- 25
- 26
- 23
- 24
- 25
- 26
- 31
- 32
- 27
- TSOPII-48
- 30
- 28
- 29
- TSOPII-56
- Flash and SRAM Memory Interface
- (C) COPYRIGHT 2023
         Texas Instruments
        All Rights Reserved
sheet 9
- RS - 232 PORT 0
- RS - 232 PORT 1
- (signal at PC)
- These components are
  installed for ultra-low
  power mode.
- (signal at PC)
- Note: This buffer prevents the USB host
  from detecting the slave device before
  ARM processor initialization.
- USB type-B jack
- 3
- SOT-23
- 1
- 2
- RS-232, Synchronous Serial Port, and USB
- (C) COPYRIGHT 2023
         Texas Instruments
        All Rights Reserved
